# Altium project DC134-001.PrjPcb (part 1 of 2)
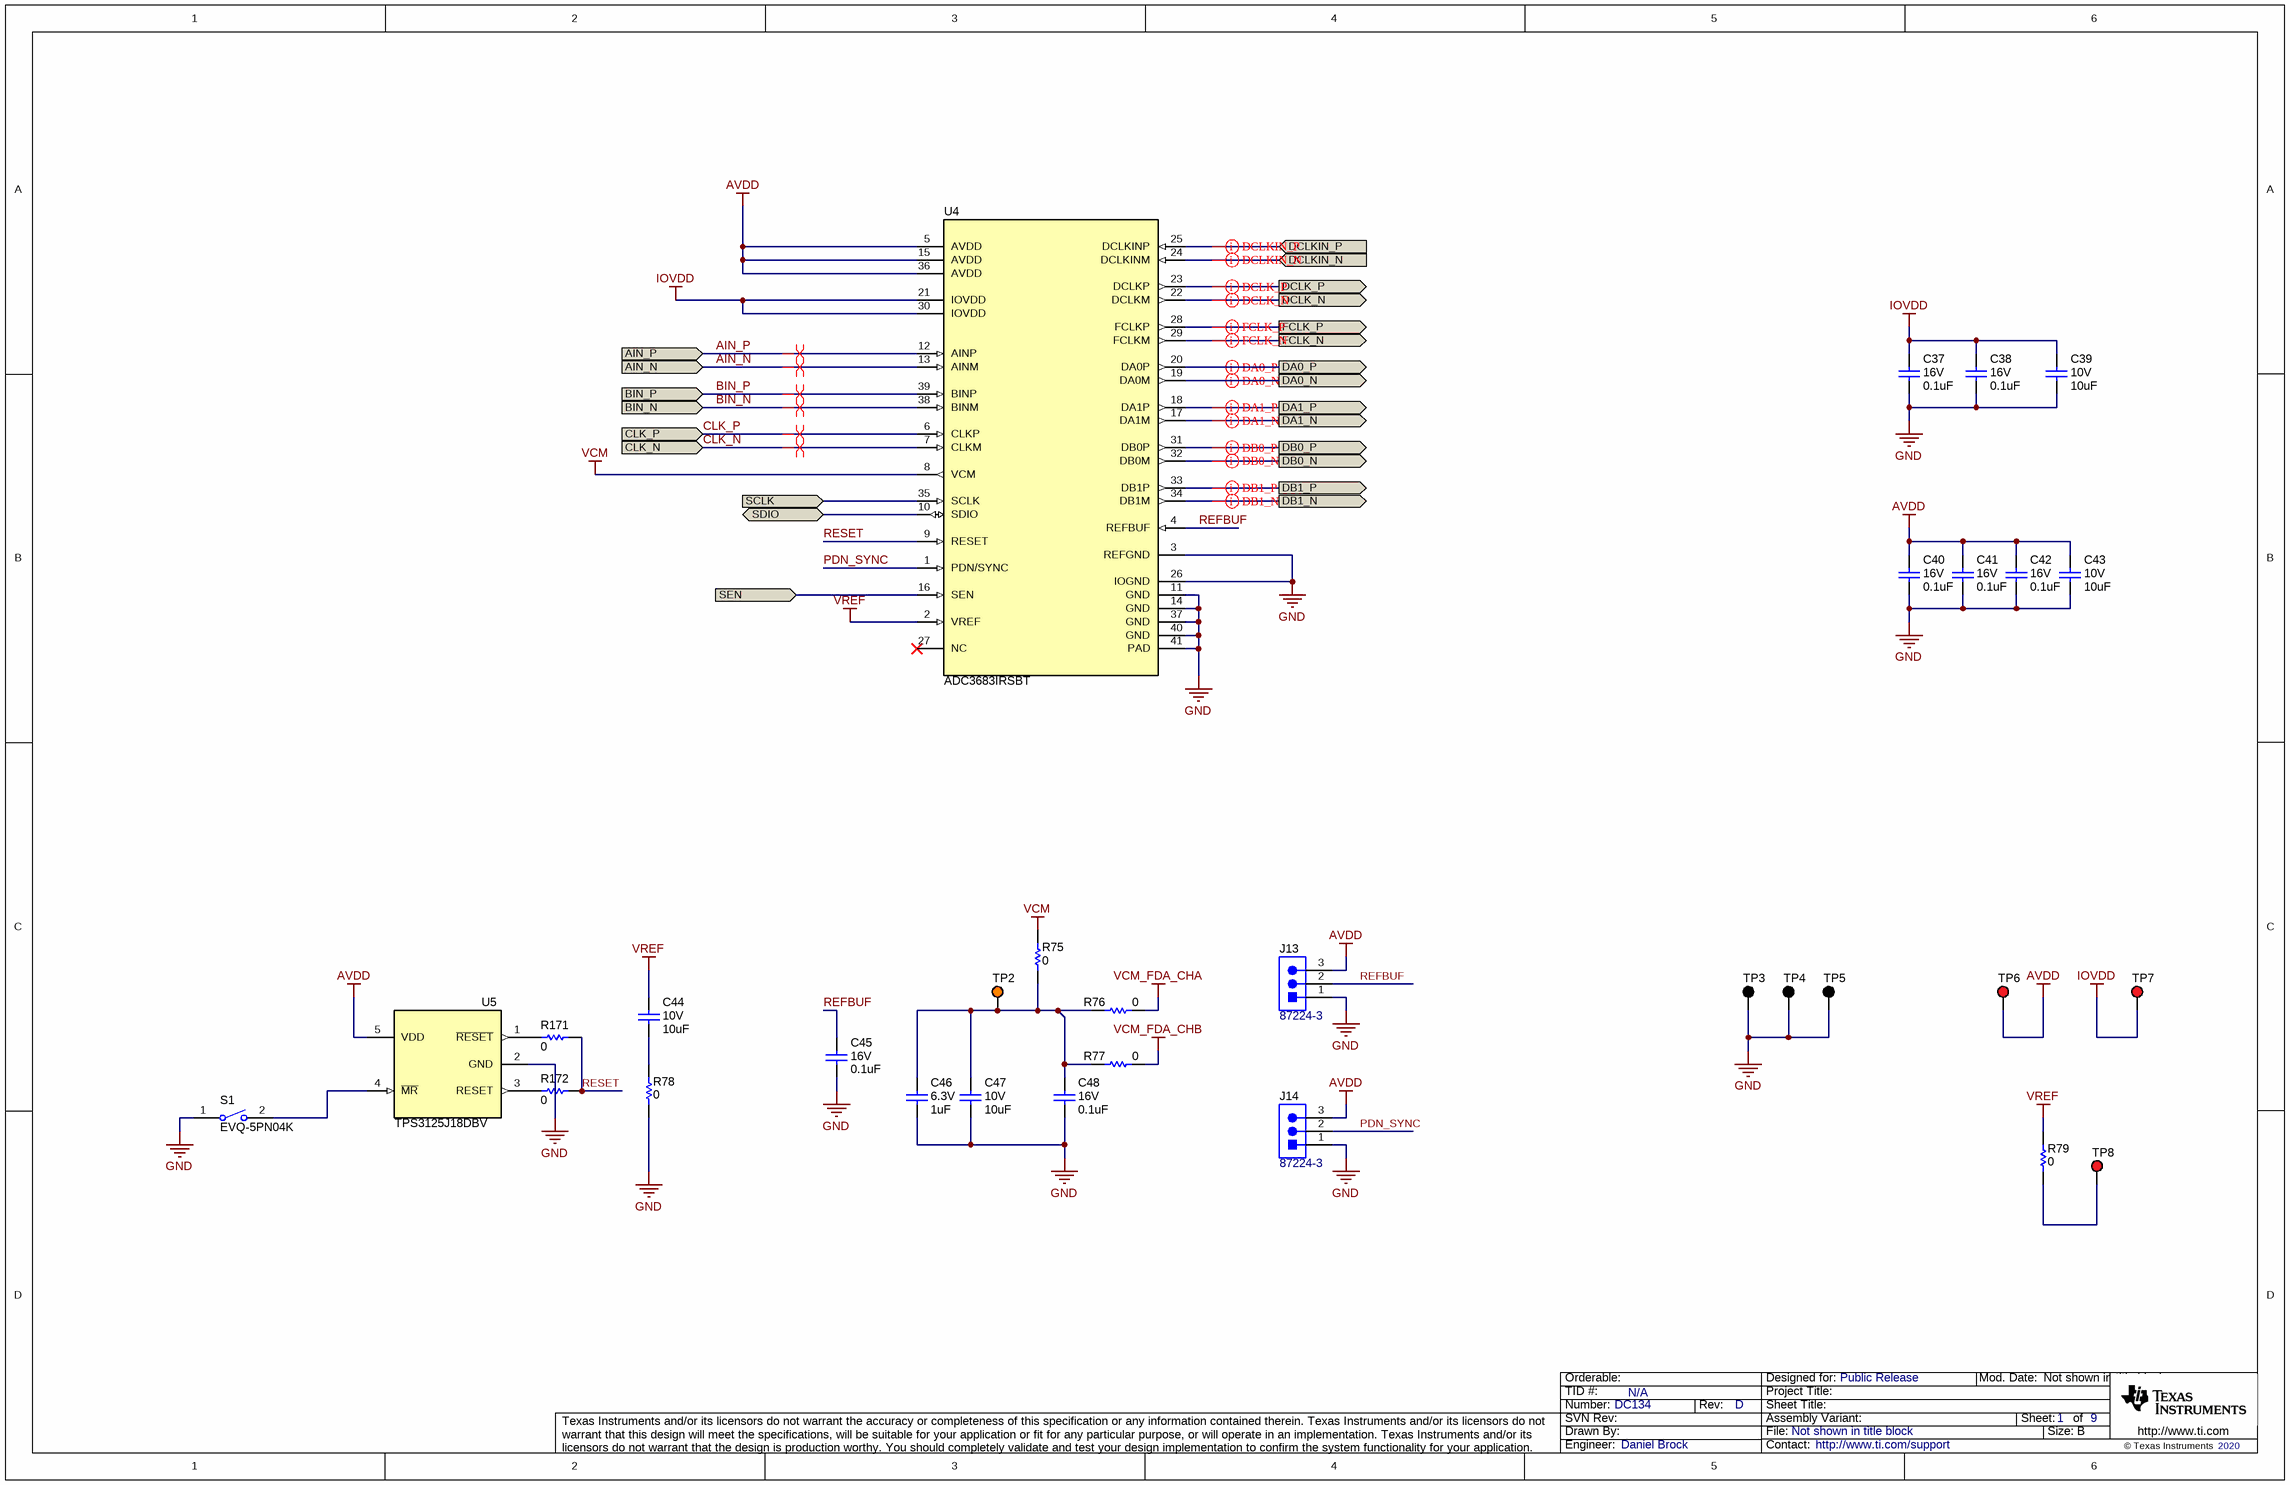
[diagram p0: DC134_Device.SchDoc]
CopyrightYear: 2020; PCB_Layout: Daniel Brock; PCB_Rev: D; PRA: ADC3683EVM; PRJ_Customer: Public Release; PRJ_Engineer: Daniel Brock; PRJ_Number: DC134; SCH_Rev: D; TechSupport: http://www.ti.com/support; TID: N/A
9 sheets, 407 parts. Net scope: flat (ports and power ports of the same name join across sheets).
Board file: DC134_PCB.PcbDoc
Sheets:
  DC134_Device.SchDoc
  DC134_AIN.SchDoc
  DC134_FDA.SchDoc
  DC134_CLK.SchDoc
  DC134_USB.SchDoc
  DC134_Power.SchDoc
  DC134_Reference.SchDoc
  DC134_FMC.SchDoc
  DC134_Hardware.SchDoc

## Sheet DC134_Device.SchDoc
size 431 x 279 mm; Date: Not shown in title block; ApprovedBy: Not shown in title block; CheckedBy: Not shown in title block; Author: Not shown in title block; CompanyName: Not shown in title block; Engineer: Not shown in title block; Organization: Not shown in title block; Address1: Not shown in title block; Address2: Not shown in title block; Address3: Not shown in title block; Address4: Not shown in title block; DocumentNumber: 1; Revision: Use project parameter SCH_Rev; SheetNumber: 1; SheetTotal: 9; PageSetup: Record=PageOptions¦CenterHorizontal=True¦CenterVertical=True¦PrintScale=1.00¦XCorrection=1.00¦YCorrection=1.00¦PrintKind=0¦BorderSize=5000000¦LeftOffset=0¦BottomOffset=0¦Orientation=2¦PaperLength=1000¦PaperWidth=1000¦Scale=100¦PaperSource=15¦PrintQuality=600¦MediaType=1¦DitherType=10¦PaperKind=Letter¦PrintScaleMode=1

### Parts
C37  VDC_V: 16V  ValueDisplayed: 0.1uF  [0201L]  (hidden comment: GRM033Z71C104KE14D)
C38  VDC_V: 16V  ValueDisplayed: 0.1uF  [0201L]  (hidden comment: GRM033Z71C104KE14D)
C39  VDC_V: 10V  ValueDisplayed: 10uF  [0603L]  (hidden comment: GRM188Z71A106MA73D)
C40  VDC_V: 16V  ValueDisplayed: 0.1uF  [0201L]  (hidden comment: GRM033Z71C104KE14D)
C41  VDC_V: 16V  ValueDisplayed: 0.1uF  [0201L]  (hidden comment: GRM033Z71C104KE14D)
C42  VDC_V: 16V  ValueDisplayed: 0.1uF  [0201L]  (hidden comment: GRM033Z71C104KE14D)
C43  VDC_V: 10V  ValueDisplayed: 10uF  [0603L]  (hidden comment: GRM188Z71A106MA73D)
C44  VDC_V: 10V  ValueDisplayed: 10uF  [0603L]  (hidden comment: GRM188Z71A106MA73D)
C45  VDC_V: 16V  ValueDisplayed: 0.1uF  [0201L]  (hidden comment: GRM033Z71C104KE14D)
C46  VDC_V: 6.3V  ValueDisplayed: 1uF  [0402L]  (hidden comment: GRM155R70J105MA12D)
C47  VDC_V: 10V  ValueDisplayed: 10uF  [0603L]  (hidden comment: GRM188Z71A106MA73D)
C48  VDC_V: 16V  ValueDisplayed: 0.1uF  [0201L]  (hidden comment: GRM033Z71C104KE14D)
J13  87224-3  [TE_87224-3]
J14  87224-3  [TE_87224-3]
R75  ValueDisplayed: 0  [0201L]  (hidden comment: CRCW02010000Z0ED)
R76  ValueDisplayed: 0  [0201L]  (hidden comment: CRCW02010000Z0ED)
R77  ValueDisplayed: 0  [0201L]  (hidden comment: CRCW02010000Z0ED)
R78  ValueDisplayed: 0  [0201L]  (hidden comment: ERJ-1GN0R00C)
R79  ValueDisplayed: 0  [0201]  (hidden comment: ERJ-1GN0R00C)
R171  ValueDisplayed: 0  [0603L]  (hidden comment: RC0603JR-070RL)
R172  ValueDisplayed: 0  [0603L]  (hidden comment: RC0603JR-070RL)
S1  EVQ-5PN04K  [SW_EVQ5PN04K]
TP2  5013  [Keystone5013]  (value not drawn)
TP3  5011  [Keystone5011]  (value not drawn)
TP4  5011  [Keystone5011]  (value not drawn)
TP5  5011  [Keystone5011]  (value not drawn)
TP6  5010  [Keystone5010]  (value not drawn)
TP7  5010  [Keystone5010]  (value not drawn)
TP8  5010  [Keystone5010]  (value not drawn)
U4  ADC3683IRSBT  [RSB0040B]
U5  TPS3125J18DBV  [DBV0005A_L]

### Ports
AIN_N (in), AIN_P (in), BIN_N (in), BIN_P (in), CLK_N (in), CLK_P (in), DA0_N (out), DA0_P (out), DA1_N (out), DA1_P (out), DB0_N (out), DB0_P (out), DB1_N (out), DB1_P (out), DCLK_N (out), DCLK_P (out), DCLKIN_N (in), DCLKIN_P (in), FCLK_N (out), FCLK_P (out), SCLK (in), SDIO (bidir), SEN (in)

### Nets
AVDD: C40.1 C41.1 C42.1 C43.1 J13.3 J14.3 TP6.1 U4.5(AVDD) U4.15(AVDD) U4.36(AVDD) U5.5(VDD)
GND: C37.2 C38.2 C39.2 C40.2 C41.2 C42.2 C43.2 C45.2 C46.2 C47.2 C48.2 J13.1 J14.1 R78.1 S1.1 TP3.1 TP4.1 TP5.1 U4.3(REFGND) U4.11(GND) U4.14(GND) U4.26(IOGND) U4.37(GND) U4.40(GND) U4.41(PAD) U5.2(GND)
IOVDD: C37.1 C38.1 C39.1 TP7.1 U4.21(IOVDD) U4.30(IOVDD)
VCM: R75.2 U4.8(VCM)
VCM_FDA_CHA: R76.2
VCM_FDA_CHB: R77.2
VREF: C44.1 R79.2 U4.2(VREF)
AIN_N: U4.13(AINM) ; port AIN_N
AIN_P: U4.12(AINP) ; port AIN_P
BIN_N: U4.38(BINM) ; port BIN_N
BIN_P: U4.39(BINP) ; port BIN_P
CLK_N: U4.7(CLKM) ; port CLK_N
CLK_P: U4.6(CLKP) ; port CLK_P
DA0_N: U4.19(DA0M) ; port DA0_N
DA0_P: U4.20(DA0P) ; port DA0_P
DA1_N: U4.17(DA1M) ; port DA1_N
DA1_P: U4.18(DA1P) ; port DA1_P
DB0_N: U4.32(DB0M) ; port DB0_N
DB0_P: U4.31(DB0P) ; port DB0_P
DB1_N: U4.34(DB1M) ; port DB1_N
DB1_P: U4.33(DB1P) ; port DB1_P
DCLK_N: U4.22(DCLKM) ; port DCLK_N
DCLK_P: U4.23(DCLKP) ; port DCLK_P
DCLKIN_N: U4.24(DCLKINM) ; port DCLKIN_N
DCLKIN_P: U4.25(DCLKINP) ; port DCLKIN_P
FCLK_N: U4.29(FCLKM) ; port FCLK_N
FCLK_P: U4.28(FCLKP) ; port FCLK_P
PDN_SYNC: J14.2 U4.1(PDN/SYNC)
REFBUF: C45.1 J13.2 U4.4(REFBUF)
RESET: R171.2 R172.2 U4.9(RESET)
SCLK: U4.35(SCLK) ; port SCLK
SDIO: U4.10(SDIO) ; port SDIO
SEN: U4.16(SEN) ; port SEN
NetC44_2: C44.2 R78.2
NetC46_1: C46.1 C47.1 C48.1 R75.1 R76.1 R77.1 TP2.1
NetR79_1: R79.1 TP8.1
NetR171_1: R171.1 U5.1(~{RESET})
NetR172_1: R172.1 U5.3(RESET)
NetS1_2: S1.2 U5.4(~{MR})

Not connected (* = marked no-connect by the designer): U4 27(NC)*

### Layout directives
differential pair: AIN_N, AIN_P, BIN_N, BIN_P, CLK_N, CLK_P, DA0_N, DA0_P, DA1_N, DA1_P, DB0_N, DB0_P, DB1_N, DB1_P, DCLK_N, DCLK_P, DCLKIN_N, DCLKIN_P, FCLK_N, FCLK_P

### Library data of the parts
C37 C38 C40-C42 C45 C48 = CMP-0064970-1: CAP, CERM, 0.1 uF, 16 V,+/- 10%, X7R, 0201; Manufacturer: MuRata; TaMin_C: -55°C; Polarized: N; SizeAreaWB_mm2: 2.08; Value1: Unknown; U/M: EA; Value: 0.1uF; TaMax_C: 125°C; SizeZ_mm: 0.26; SizeX_mm: 0.6; SizeY_mm: 0.3; Cap_Case: 0201; SizeArea_mm2: 0.18; CompType: Capacitor; Cap_F: 100nF; AEC Category: Q200
C39 C43 C44 C47 = CMP-0007497-5: CAP, CERM, 10 uF, 10 V, +/- 20%, X7R, 0603; Manufacturer: MuRata; TaMin_C: -55°C; Polarized: N; SizeAreaWB_mm2: 4.68; Value1: Unknown; U/M: EA; Value: 10uF; TaMax_C: 125°C; SizeZ_mm: 1; SizeX_mm: 1.6; SizeY_mm: 0.8; Cap_Case: 0603; SizeArea_mm2: 1.28; Cap_F: 10µF; AEC Category: Q200
C46 = CMP-0006624-2: CAP, CERM, 1 uF, 6.3 V, +/- 20%, X7R, 0402; Manufacturer: MuRata; TaMin_C: -55°C; Polarized: N; SizeAreaWB_mm2: 3; Value1: Unknown; U/M: EA; Value: 1uF; TaMax_C: 125°C; SizeZ_mm: 0.6; SizeX_mm: 1; SizeY_mm: 0.5; Cap_Case: 0402; Cap_F: 1µF; AEC Category: Q200
J13 J14 = CMP-0078139-1: Header, 2.54mm, 3x1, Gold, TH; Manufacturer: TE Connectivity; Pitch_mm: 2.54; Gender: Male; Cert_UL: Y; Current_A: 3A; Voltage_V: 750V; Green_REACh: Passed; Shrouded: N; Green_Lifecycle: Active; Row_Count: 1
R75-R77 = CMP-0027008-4: RES, 0, 5%, 0.05 W, 0201; Manufacturer: Vishay-Dale; Power_W: 50mW; TempCo: ppm/C; Value_Code: 0000; Value: 0; EIA_Code: E24; SizeX_mm: 0.6; SizeY_mm: 0.3; SizeZ_mm: 0.26; Value2: 0.05W; SizeArea_mm2: 0.18; CompType: Resistor; AEC Qualified: N; AEC Category: Q200
R78 R79 = CMP-0065361-1: RES, 0, 5%, .05 W, AEC-Q200 Grade 0, 0201; Manufacturer: Panasonic; Power_W: 50mW; Green_Lifecycle: Not Set; TempCo: ppm/C; Value_Code: 0000; Green_REACh: Incomplete; U/M: EA; Value: 0; EIA_Code: E24; SizeX_mm: 0.6; SizeY_mm: 0.3; SizeZ_mm: 0.26; Value2: .05W; SizeArea_mm2: 0.18; CompType: Resistor; AEC Qualified: Y; AEC Category: Q200
R171 R172 = CMP-0025885-5: RES, 0, 5%, 0.1 W, 0603; Manufacturer: Yageo; Power_W: 100mW; TempCo: 200 ppm/C; Value_Code: 0000; Value: 0; EIA_Code: E24; SizeX_mm: 1.6; SizeZ_mm: 1; Value2: 0.1W; SizeArea_mm2: 1.28; AEC Qualified: N; VDC_V: 75V; AEC Category: Q200; SizeY_mm: 0.8; SizeAreaWB_mm2: 4.68
S1 = CMP-0002323-1: Switch, SPST-NO, Off-Mom, 0.05 A, 12 VDC, SMD; Manufacturer: Panasonic; CurrentRating_mA: 50A; PositionCount: 1; SizeX_mm: 7.2; SizeY_mm: 3.5; SizeZ_mm: 4.3; SizeArea_mm2: 25.2; VDC_V: 12V; SizeAreaWB_mm2: 50.6
TP2 = CMP-0055150-2: Test Point, Multipurpose, Orange, TH; Manufacturer: Keystone Electronics; CT: TRUE; ContactFinish: Silver; Green_REACh: Passed; CNHeader: FALSE; Green_Lifecycle: Active
TP3-TP5 = CMP-0055148-1: Test Point, Multipurpose, Black, TH; Manufacturer: Keystone; CNHeader: FALSE; Green_Lifecycle: Active; Green_REACh: Passed; ContactFinish: Silver; CT: TRUE
TP6-TP8 = CMP-0055147-2: Test Point, Multipurpose, Red, TH; Manufacturer: Keystone Electronics; CT: TRUE; ContactFinish: Silver; Green_Lifecycle: Active; CNHeader: FALSE; Green_REACh: Passed
U4 = CMP-0080419-4: 18-bit 65 MSPS Low Noise Ultra-low Power Dual Channel ADC, RSB0040B (WQFN-40); Alternate Manufacturer: Texas Instruments; SizeArea_mm2: 25; SizeZ_mm: 0.8; AEC Category: Q200; SizeY_mm: 5; SizeAreaWB_mm2: 49; AEC Qualified: N; CompType: IC
U5 = cmp00115: Push-pull, supply voltage supervisor with manual reset; Manufacturer: Texas Instruments; CompType: Voltage Detector

## Sheet DC134_AIN.SchDoc
size 431 x 279 mm; Date: Not shown in title block; ApprovedBy: Not shown in title block; CheckedBy: Not shown in title block; Author: Not shown in title block; CompanyName: Not shown in title block; Engineer: Not shown in title block; Organization: Not shown in title block; Address1: Not shown in title block; Address2: Not shown in title block; Address3: Not shown in title block; Address4: Not shown in title block; DocumentNumber: 2; Revision: Use project parameter SCH_Rev; SheetNumber: 2; SheetTotal: 9; PageSetup: Record=PageOptions¦CenterHorizontal=True¦CenterVertical=True¦PrintScale=1.00¦XCorrection=1.00¦YCorrection=1.00¦PrintKind=0¦BorderSize=5000000¦LeftOffset=0¦BottomOffset=0¦Orientation=2¦PaperLength=1000¦PaperWidth=1000¦Scale=100¦PaperSource=15¦PrintQuality=600¦MediaType=1¦DitherType=10¦PaperKind=Letter¦PrintScaleMode=1
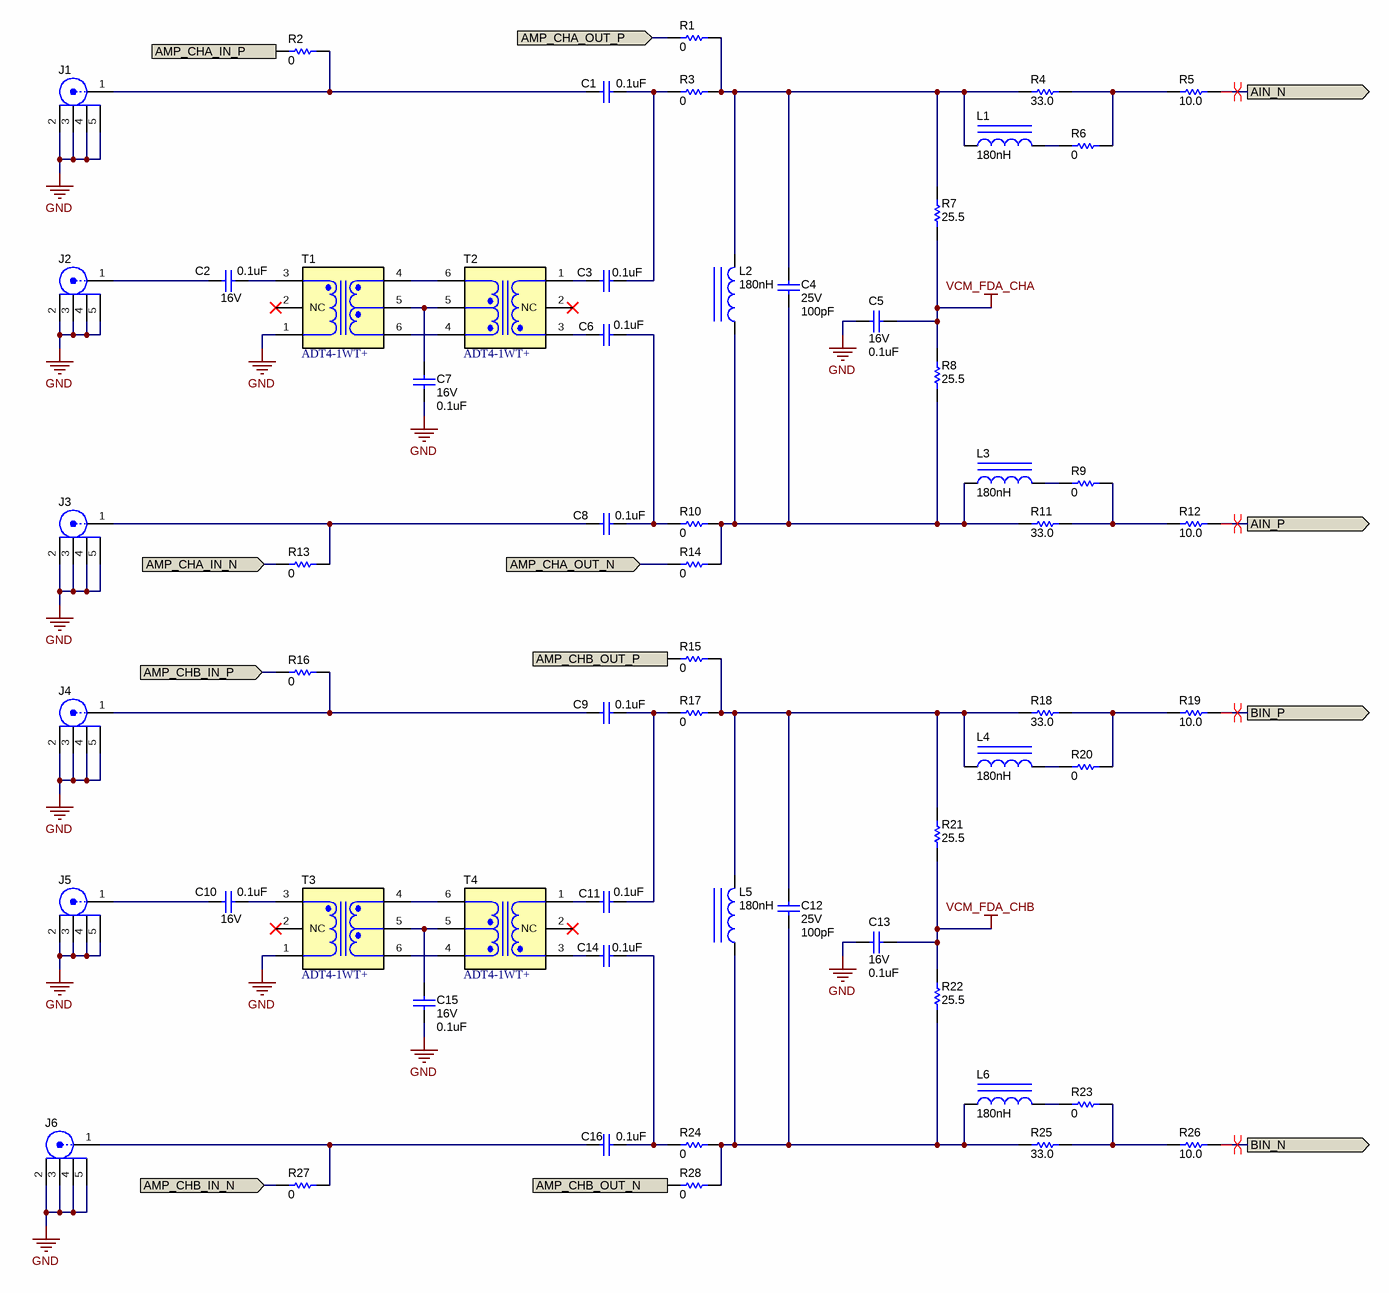
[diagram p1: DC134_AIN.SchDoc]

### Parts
C1  ValueDisplayed: 0.1uF  [0201L]  (hidden comment: GRM033Z71C104KE14D)
C2  VDC_V: 16V  ValueDisplayed: 0.1uF  [0201L]  (hidden comment: GRM033Z71C104KE14D)
C3  ValueDisplayed: 0.1uF  [0201L]  (hidden comment: GRM033Z71C104KE14D)
C4  VDC_V: 25V  ValueDisplayed: 100pF  [0201]  (hidden comment: GRM033R71E101KA01D)
C5  VDC_V: 16V  ValueDisplayed: 0.1uF  [0201L]  (hidden comment: GRM033Z71C104KE14D)
C6  ValueDisplayed: 0.1uF  [0201L]  (hidden comment: GRM033Z71C104KE14D)
C7  VDC_V: 16V  ValueDisplayed: 0.1uF  [0201L]  (hidden comment: GRM033Z71C104KE14D)
C8  ValueDisplayed: 0.1uF  [0201L]  (hidden comment: GRM033Z71C104KE14D)
C9  ValueDisplayed: 0.1uF  [0201L]  (hidden comment: GRM033Z71C104KE14D)
C10  VDC_V: 16V  ValueDisplayed: 0.1uF  [0201L]  (hidden comment: GRM033Z71C104KE14D)
C11  ValueDisplayed: 0.1uF  [0201L]  (hidden comment: GRM033Z71C104KE14D)
C12  VDC_V: 25V  ValueDisplayed: 100pF  [0201]  (hidden comment: GRM033R71E101KA01D)
C13  VDC_V: 16V  ValueDisplayed: 0.1uF  [0201L]  (hidden comment: GRM033Z71C104KE14D)
C14  ValueDisplayed: 0.1uF  [0201L]  (hidden comment: GRM033Z71C104KE14D)
C15  VDC_V: 16V  ValueDisplayed: 0.1uF  [0201L]  (hidden comment: GRM033Z71C104KE14D)
C16  ValueDisplayed: 0.1uF  [0201L]  (hidden comment: GRM033Z71C104KE14D)
J1  142-0701-801  [Johnson_142-0701-801]  (value not drawn)
J2  901-144-8RFX  [AMPHENOL_901-144-8RFX]  (value not drawn)
J3  142-0701-801  [Johnson_142-0701-801]  (value not drawn)
J4  142-0701-801  [Johnson_142-0701-801]  (value not drawn)
J5  901-144-8RFX  [AMPHENOL_901-144-8RFX]  (value not drawn)
J6  142-0701-801  [Johnson_142-0701-801]  (value not drawn)
L1  ValueDisplayed: 180nH  [IND_LQG15H]  (hidden comment: LQG15HSR18J02D)
L2  ValueDisplayed: 180nH  [IND_LQG15H]  (hidden comment: LQG15HSR18J02D)
L3  ValueDisplayed: 180nH  [IND_LQG15H]  (hidden comment: LQG15HSR18J02D)
L4  ValueDisplayed: 180nH  [IND_LQG15H]  (hidden comment: LQG15HSR18J02D)
L5  ValueDisplayed: 180nH  [IND_LQG15H]  (hidden comment: LQG15HSR18J02D)
L6  ValueDisplayed: 180nH  [IND_LQG15H]  (hidden comment: LQG15HSR18J02D)
R1  ValueDisplayed: 0  [0201L]  (hidden comment: CRCW02010000Z0ED)
R2  ValueDisplayed: 0  [0201L]  (hidden comment: CRCW02010000Z0ED)
R3  ValueDisplayed: 0  [0201L]  (hidden comment: CRCW02010000Z0ED)
R4  ValueDisplayed: 33.0  [0201]  (hidden comment: RC0201FR-7D33RL)
R5  ValueDisplayed: 10.0  [0201]  (hidden comment: RC0201FR-7D10RL)
R6  ValueDisplayed: 0  [0201L]  (hidden comment: CRCW02010000Z0ED)
R7  ValueDisplayed: 25.5  [0201L]  (hidden comment: RC0201FR-0725R5L)
R8  ValueDisplayed: 25.5  [0201L]  (hidden comment: RC0201FR-0725R5L)
R9  ValueDisplayed: 0  [0201L]  (hidden comment: CRCW02010000Z0ED)
R10  ValueDisplayed: 0  [0201L]  (hidden comment: CRCW02010000Z0ED)
R11  ValueDisplayed: 33.0  [0201]  (hidden comment: RC0201FR-7D33RL)
R12  ValueDisplayed: 10.0  [0201]  (hidden comment: RC0201FR-7D10RL)
R13  ValueDisplayed: 0  [0201L]  (hidden comment: CRCW02010000Z0ED)
R14  ValueDisplayed: 0  [0201L]  (hidden comment: CRCW02010000Z0ED)
R15  ValueDisplayed: 0  [0201L]  (hidden comment: CRCW02010000Z0ED)
R16  ValueDisplayed: 0  [0201L]  (hidden comment: CRCW02010000Z0ED)
R17  ValueDisplayed: 0  [0201L]  (hidden comment: CRCW02010000Z0ED)
R18  ValueDisplayed: 33.0  [0201]  (hidden comment: RC0201FR-7D33RL)
R19  ValueDisplayed: 10.0  [0201]  (hidden comment: RC0201FR-7D10RL)
R20  ValueDisplayed: 0  [0201L]  (hidden comment: CRCW02010000Z0ED)
R21  ValueDisplayed: 25.5  [0201L]  (hidden comment: RC0201FR-0725R5L)
R22  ValueDisplayed: 25.5  [0201L]  (hidden comment: RC0201FR-0725R5L)
R23  ValueDisplayed: 0  [0201L]  (hidden comment: CRCW02010000Z0ED)
R24  ValueDisplayed: 0  [0201L]  (hidden comment: CRCW02010000Z0ED)
R25  ValueDisplayed: 33.0  [0201]  (hidden comment: RC0201FR-7D33RL)
R26  ValueDisplayed: 10.0  [0201]  (hidden comment: RC0201FR-7D10RL)
R27  ValueDisplayed: 0  [0201L]  (hidden comment: CRCW02010000Z0ED)
R28  ValueDisplayed: 0  [0201L]  (hidden comment: CRCW02010000Z0ED)
T1  ADT4-1WT+  [MNC_CD542]
T2  ADT4-1WT+  [MNC_CD542]
T3  ADT4-1WT+  [MNC_CD542]
T4  ADT4-1WT+  [MNC_CD542]

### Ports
AIN_N (out), AIN_P (out), AMP_CHA_IN_N (in), AMP_CHA_IN_P (in), AMP_CHA_OUT_N (in), AMP_CHA_OUT_P (in), AMP_CHB_IN_N (in), AMP_CHB_IN_P (in), AMP_CHB_OUT_N (in), AMP_CHB_OUT_P (in), BIN_N (out), BIN_P (out)

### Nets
GND: C5.1 C7.1 C13.1 C15.1 J1.2 J1.3 J1.4 J1.5 J2.2 J2.3 J2.4 J2.5 J3.2 J3.3 J3.4 J3.5 J4.2 J4.3 J4.4 J4.5 J5.2 J5.3 J5.4 J5.5 J6.2 J6.3 J6.4 J6.5 T1.1 T3.1
VCM_FDA_CHA: C5.2 R7.1 R8.2
VCM_FDA_CHB: C13.2 R21.1 R22.2
AIN_N: R5.2 ; port AIN_N
AIN_P: R12.2 ; port AIN_P
AMP_CHA_IN_N: R13.1 ; port AMP_CHA_IN_N
AMP_CHA_IN_P: R2.1 ; port AMP_CHA_IN_P
AMP_CHA_OUT_N: R14.1 ; port AMP_CHA_OUT_N
AMP_CHA_OUT_P: R1.1 ; port AMP_CHA_OUT_P
AMP_CHB_IN_N: R27.1 ; port AMP_CHB_IN_N
AMP_CHB_IN_P: R16.1 ; port AMP_CHB_IN_P
AMP_CHB_OUT_N: R28.1 ; port AMP_CHB_OUT_N
AMP_CHB_OUT_P: R15.1 ; port AMP_CHB_OUT_P
BIN_N: R26.2 ; port BIN_N
BIN_P: R19.2 ; port BIN_P
NetC1_1: C1.1 J1.1 R2.2
NetC1_2: C1.2 C3.2 R3.1
NetC2_1: C2.1 J2.1
NetC2_2: C2.2 T1.3
NetC3_1: C3.1 T2.1
NetC4_1: C4.1 L1.1 L2.2 R1.2 R3.2 R4.1 R7.2
NetC4_2: C4.2 L2.1 L3.1 R8.1 R10.2 R11.1 R14.2
NetC6_1: C6.1 T2.3
NetC6_2: C6.2 C8.2 R10.1
NetC7_2: C7.2 T1.5 T2.5
NetC8_1: C8.1 J3.1 R13.2
NetC9_1: C9.1 J4.1 R16.2
NetC9_2: C9.2 C11.2 R17.1
NetC10_1: C10.1 J5.1
NetC10_2: C10.2 T3.3
NetC11_1: C11.1 T4.1
NetC12_1: C12.1 L4.1 L5.2 R15.2 R17.2 R18.1 R21.2
NetC12_2: C12.2 L5.1 L6.1 R22.1 R24.2 R25.1 R28.2
NetC14_1: C14.1 T4.3
NetC14_2: C14.2 C16.2 R24.1
NetC15_2: C15.2 T3.5 T4.5
NetC16_1: C16.1 J6.1 R27.2
NetL1_2: L1.2 R6.1
NetL3_2: L3.2 R9.1
NetL4_2: L4.2 R20.1
NetL6_2: L6.2 R23.1
NetR4_2: R4.2 R5.1 R6.2
NetR9_2: R9.2 R11.2 R12.1
NetR18_2: R18.2 R19.1 R20.2
NetR23_2: R23.2 R25.2 R26.1
NetT1_4: T1.4 T2.6
NetT1_6: T1.6 T2.4
NetT3_4: T3.4 T4.6
NetT3_6: T3.6 T4.4

Not connected (* = marked no-connect by the designer): T1 2(NC)*; T2 2(NC)*; T3 2(NC)*; T4 2(NC)*

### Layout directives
differential pair: AIN_N, AIN_P, BIN_N, BIN_P

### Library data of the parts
C1 C3 C6 C8 C9 C11 C14 C16 = CMP-0064970-1: CAP, CERM, 0.1 uF, 16 V,+/- 10%, X7R, 0201; Manufacturer: MuRata; TaMin_C: -55°C; Polarized: N; SizeAreaWB_mm2: 2.08; Value1: Unknown; U/M: EA; Value: 0.1uF; TaMax_C: 125°C; SizeZ_mm: 0.26; SizeX_mm: 0.6; SizeY_mm: 0.3; Cap_Case: 0201; Value2: 16V; SizeArea_mm2: 0.18; CompType: Capacitor; Cap_F: 100nF; AEC Category: Q200
C2 C5 C7 C10 C13 C15 = CMP-0064970-1: as C37 on sheet DC134_Device
C4 C12 = CMP-0009763-1: CAP, CERM, 100 pF, 25 V, +/- 10%, X7R, 0201; Manufacturer: MuRata; TaMin_C: -55°C; Polarized: N; SizeAreaWB_mm2: 2.08; Value1: Unknown; U/M: EA; Value: 100pF; TaMax_C: 125°C; SizeZ_mm: 0.26; SizeX_mm: 0.6; SizeY_mm: 0.3; SizeArea_mm2: 0.18; AEC Category: Q200
J1 J3 J4 J6 = CMP-0055828-1: Connector, End launch SMA, 50 ohm, SMT; Manufacturer: Cinch Connectivity; CNHeader: FALSE; Green_Lifecycle: Not Set; Green_REACh: Incomplete; CT: TRUE
J2 J5 = CMP-0055833-1: SMA Straight Jack, Gold, 50 Ohm, TH; Manufacturer: Amphenol RF; CNHeader: FALSE; Green_Lifecycle: Not Set; Green_REACh: Incomplete; CT: TRUE
L1-L6 = CMP-0058650-1: Inductor, Multilayer, Air Core, 180 nH, 0.14 A, 3.38 ohm, SMD; Manufacturer: MuRata; Isat: 0.14A @ % inductance drop; Irms: 0.14A @ C rise; Green_Lifecycle: Active; SizeAreaWB_mm2: 3; DCR_ohm: 3.38; Green_REACh: Passed; Value: 180nH; Imax_A: 140mA; SizeZ_mm: 0.55; SizeX_mm: 1; SizeY_mm: 0.5; Value2: 0.14A; AEC Category: Q200
R1-R3 R6 R9 R10 R13-R17 R20 R23 R24 R27 R28 = CMP-0027008-4: RES, 0, 5%, 0.05 W, 0201; Manufacturer: Vishay-Dale; Power_W: 50mW; TempCo: ppm/C; Value_Code: 0000; Value: 0; EIA_Code: E24; SizeX_mm: 0.6; SizeY_mm: 0.3; SizeZ_mm: 0.26; Value2: 0.05W; SizeArea_mm2: 0.18; AEC Qualified: N; AEC Category: Q200
R4 R11 R18 R25 = CMP-0028006-1: RES, 33.0, 1%, 0.05 W, 0201; Manufacturer: Yageo America; Power_W: 50mW; TempCo: 200 ppm/C; Value_Code: 33R0; U/M: EA; Value: 33.0; Res_ohm: 33; SizeX_mm: 0.6; SizeY_mm: 0.3; SizeZ_mm: 0.26; Value2: 0.05W; SizeArea_mm2: 0.18; AEC Qualified: N; VDC_V: 25V; AEC Category: Q200
R5 R12 R19 R26 = CMP-0027946-1: RES, 10.0, 1%, 0.05 W, 0201; Manufacturer: Yageo America; Power_W: 50mW; TempCo: 350 ppm/C; Value_Code: 10R0; U/M: EA; Value: 10.0; EIA_Code: E96; Res_ohm: 10; SizeX_mm: 0.6; SizeY_mm: 0.3; SizeZ_mm: 0.26; Value2: 0.05W; SizeArea_mm2: 0.18; AEC Qualified: N; VDC_V: 25V; AEC Category: Q200
R7 R8 R21 R22 = CMP-0027524-1: RES, 25.5, 1%, 0.05 W, 0201; Manufacturer: Yageo America; Power_W: 50mW; TempCo: 200 ppm/C; Value_Code: 25R5; U/M: EA; Value: 25.5; EIA_Code: E96; SizeX_mm: 0.6; SizeY_mm: 0.3; SizeZ_mm: 0.26; Value2: 0.05W; SizeArea_mm2: 0.18; CompType: Resistor; AEC Qualified: N; VDC_V: 25V; AEC Category: Q200
T1-T4 = CMP-0030461-2: RF Transformer, 50 ohm, 2 to 775 MHz, SMT; Manufacturer: Minicircuits; Green_REACh: Incomplete; Green_Lifecycle: Not Set

## Sheet DC134_FDA.SchDoc
size 431 x 279 mm; Date: Not shown in title block; ApprovedBy: Not shown in title block; CheckedBy: Not shown in title block; Author: Not shown in title block; CompanyName: Not shown in title block; Engineer: Not shown in title block; Organization: Not shown in title block; Address1: Not shown in title block; Address2: Not shown in title block; Address3: Not shown in title block; Address4: Not shown in title block; DocumentNumber: 3; Revision: Use project parameter SCH_Rev; SheetNumber: 3; SheetTotal: 9; PageSetup: Record=PageOptions¦CenterHorizontal=True¦CenterVertical=True¦PrintScale=1.00¦XCorrection=1.00¦YCorrection=1.00¦PrintKind=0¦BorderSize=5000000¦LeftOffset=0¦BottomOffset=0¦Orientation=2¦PaperLength=1000¦PaperWidth=1000¦Scale=100¦PaperSource=15¦PrintQuality=600¦MediaType=1¦DitherType=10¦PaperKind=Letter¦PrintScaleMode=1
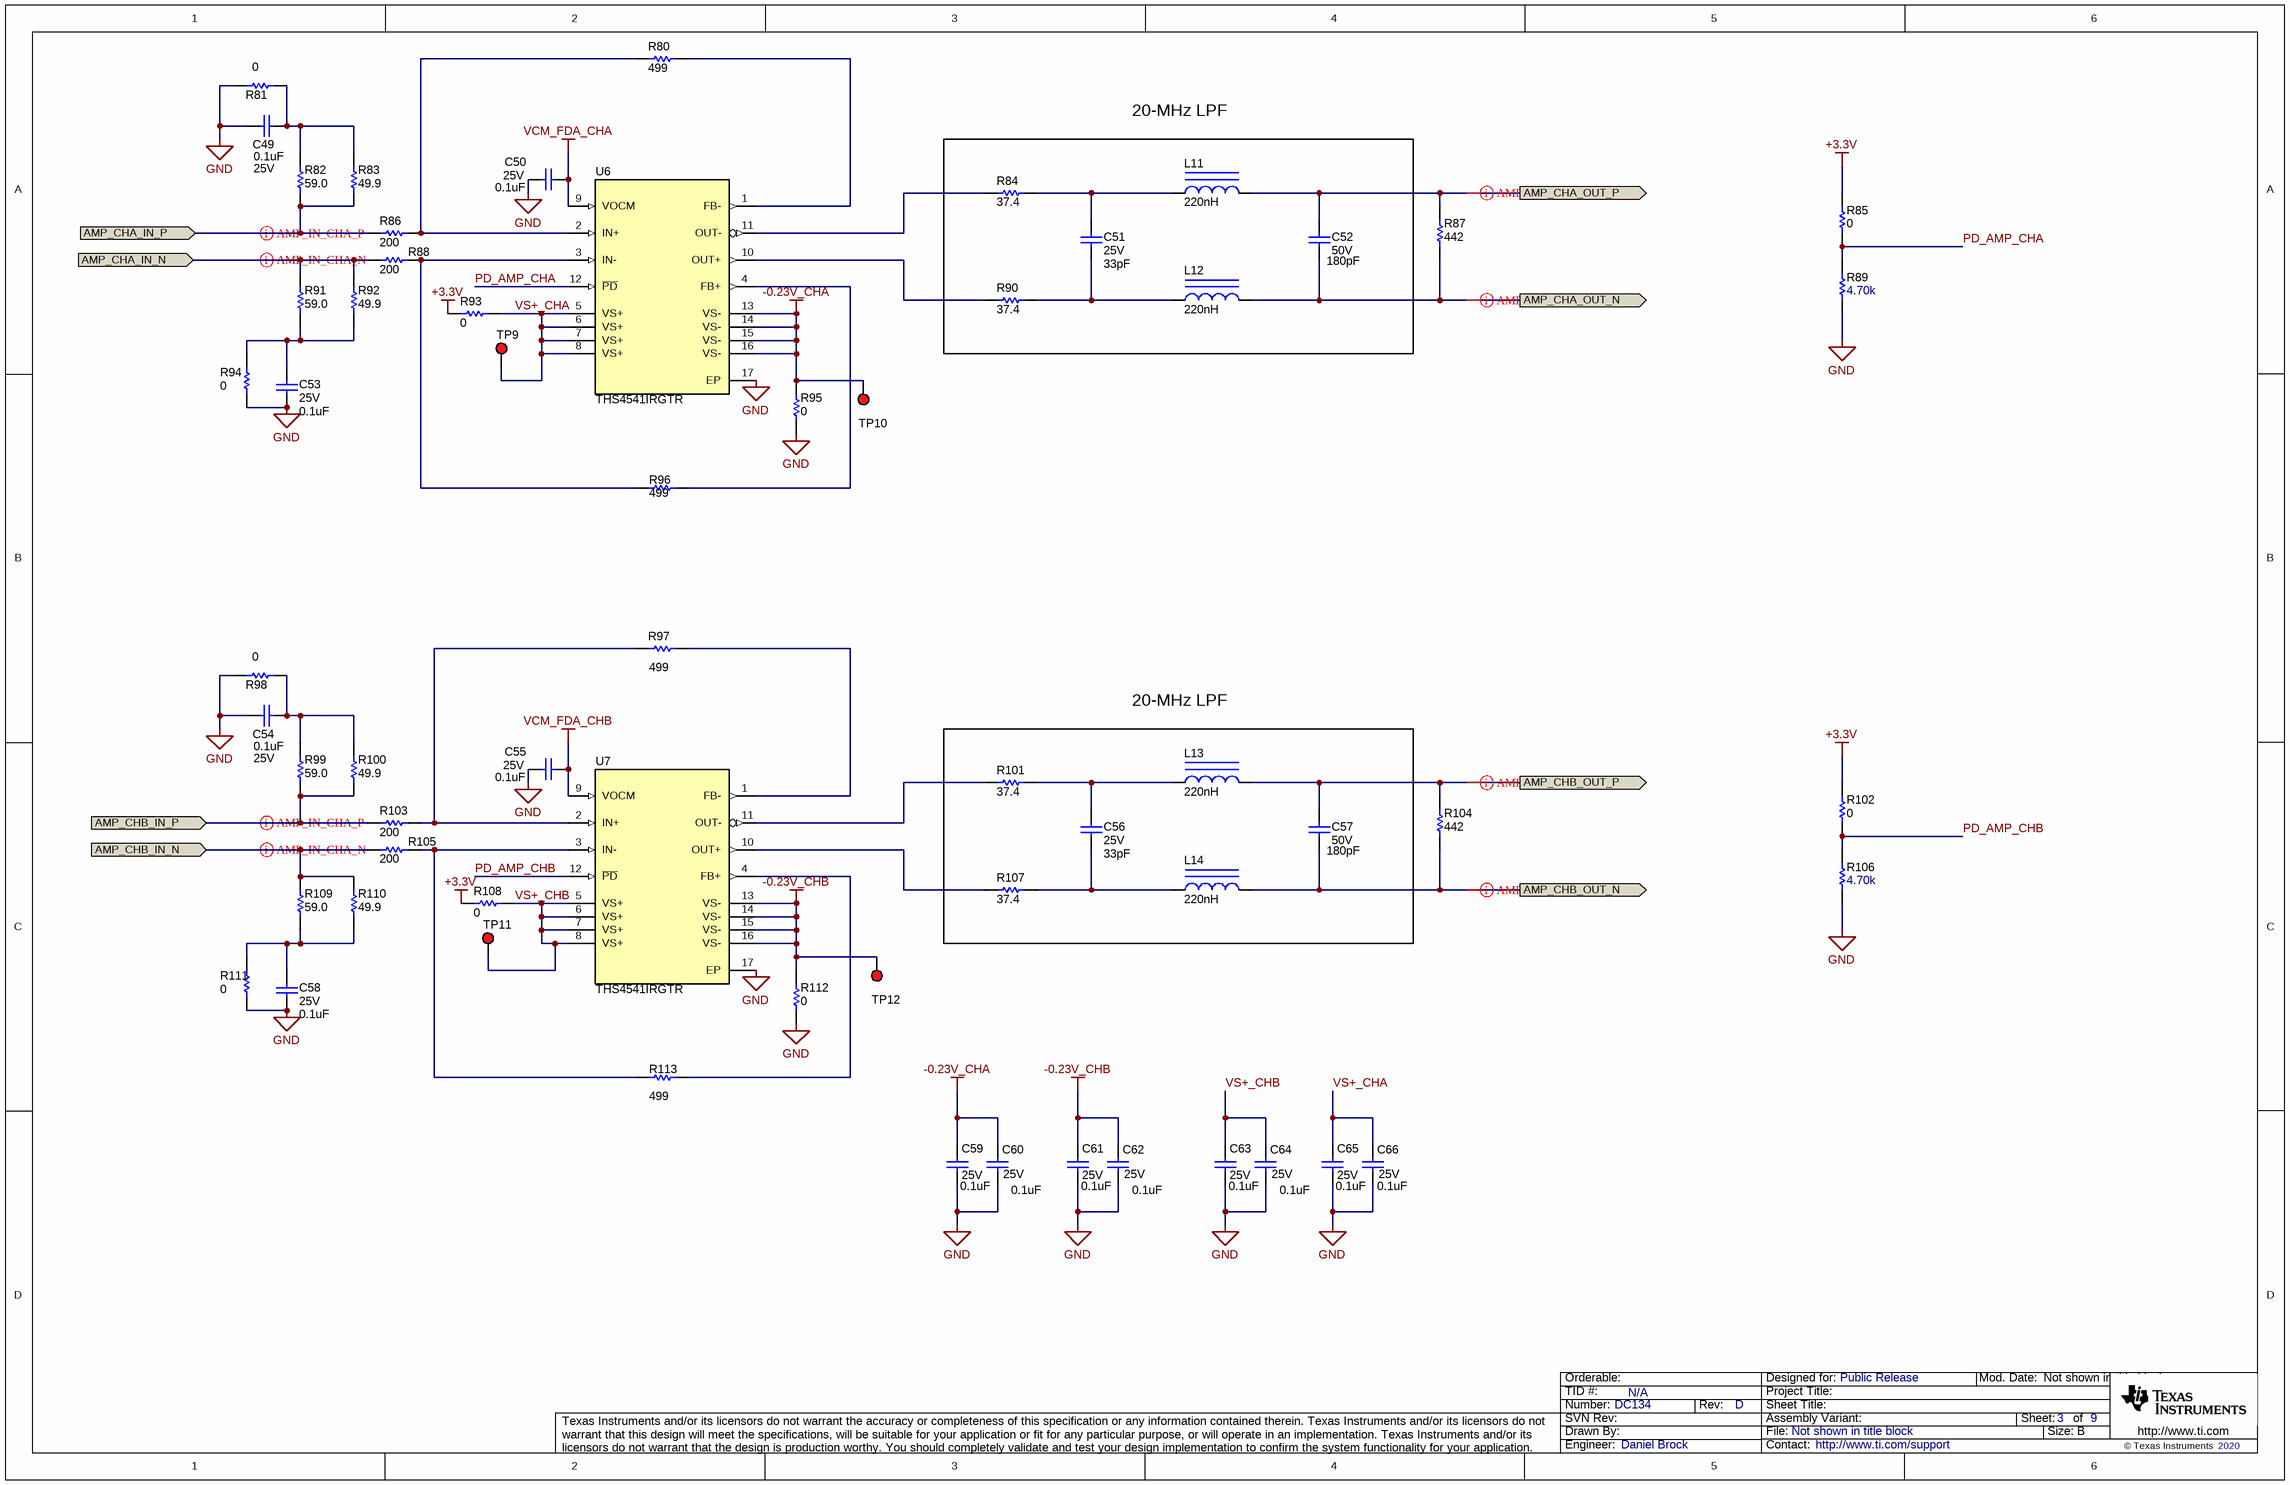
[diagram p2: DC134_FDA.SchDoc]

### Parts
C49  VDC_V: 25V  ValueDisplayed: 0.1uF  [0402]  (hidden comment: GRM155R61E104KA87D)
C50  VDC_V: 25V  ValueDisplayed: 0.1uF  [0402]  (hidden comment: GRM155R61E104KA87D)
C51  VDC_V: 25V  ValueDisplayed: 33pF  [0402]  (hidden comment: GRM1555C1E330JA01D)
C52  VDC_V: 50V  ValueDisplayed: 180pF  [0402]  (hidden comment: GRM1555C1H181JA01D)
C53  VDC_V: 25V  ValueDisplayed: 0.1uF  [0402]  (hidden comment: GRM155R61E104KA87D)
C54  VDC_V: 25V  ValueDisplayed: 0.1uF  [0402]  (hidden comment: GRM155R61E104KA87D)
C55  VDC_V: 25V  ValueDisplayed: 0.1uF  [0402]  (hidden comment: GRM155R61E104KA87D)
C56  VDC_V: 25V  ValueDisplayed: 33pF  [0402]  (hidden comment: GRM1555C1E330JA01D)
C57  VDC_V: 50V  ValueDisplayed: 180pF  [0402]  (hidden comment: GRM1555C1H181JA01D)
C58  VDC_V: 25V  ValueDisplayed: 0.1uF  [0402]  (hidden comment: GRM155R61E104KA87D)
C59  VDC_V: 25V  ValueDisplayed: 0.1uF  [0402]  (hidden comment: GRM155R61E104KA87D)
C60  value 0.1uF  VDC_V: 25V  [0402]  (hidden comment: GRM155R61E104KA87D)
C61  VDC_V: 25V  ValueDisplayed: 0.1uF  [0402]  (hidden comment: GRM155R61E104KA87D)
C62  value 0.1uF  VDC_V: 25V  [0402]  (hidden comment: GRM155R61E104KA87D)
C63  VDC_V: 25V  ValueDisplayed: 0.1uF  [0402]  (hidden comment: GRM155R61E104KA87D)
C64  value 0.1uF  VDC_V: 25V  [0402]  (hidden comment: GRM155R61E104KA87D)
C65  VDC_V: 25V  ValueDisplayed: 0.1uF  [0402]  (hidden comment: GRM155R61E104KA87D)
C66  VDC_V: 25V  ValueDisplayed: 0.1uF  [0402]  (hidden comment: GRM155R61E104KA87D)
L11  ValueDisplayed: 220nH  [IND_LQG15H]  (hidden comment: LQG15HSR22J02D)
L12  ValueDisplayed: 220nH  [IND_LQG15H]  (hidden comment: LQG15HSR22J02D)
L13  ValueDisplayed: 220nH  [IND_LQG15H]  (hidden comment: LQG15HSR22J02D)
L14  ValueDisplayed: 220nH  [IND_LQG15H]  (hidden comment: LQG15HSR22J02D)
R80  ValueDisplayed: 499  [0402]  (hidden comment: CRCW0402499RFKED)
R81  ValueDisplayed: 0  [0402]  (hidden comment: CRCW04020000Z0ED)
R82  ValueDisplayed: 59.0  [0402]  (hidden comment: CRCW040259R0FKED)
R83  ValueDisplayed: 49.9  [0402]  (hidden comment: CRCW040249R9FKED)
R84  ValueDisplayed: 37.4  [0402]  (hidden comment: CRCW040237R4FKED)
R85  ValueDisplayed: 0  [0402]  (hidden comment: CRCW04020000Z0ED)
R86  ValueDisplayed: 200  [0402]  (hidden comment: CRCW0402200RFKED)
R87  ValueDisplayed: 442  [0402]  (hidden comment: CRCW0402442RFKED)
R88  ValueDisplayed: 200  [0402]  (hidden comment: CRCW0402200RFKED)
R89  ValueDisplayed: 4.70k  [0402]  (hidden comment: ERJ-2RKF4701X)
R90  ValueDisplayed: 37.4  [0402]  (hidden comment: CRCW040237R4FKED)
R91  ValueDisplayed: 59.0  [0402]  (hidden comment: CRCW040259R0FKED)
R92  ValueDisplayed: 49.9  [0402]  (hidden comment: CRCW040249R9FKED)
R93  ValueDisplayed: 0  [0201L]  (hidden comment: CRCW02010000Z0ED)
R94  ValueDisplayed: 0  [0402]  (hidden comment: CRCW04020000Z0ED)
R95  ValueDisplayed: 0  [0201L]  (hidden comment: CRCW02010000Z0ED)
R96  ValueDisplayed: 499  [0402]  (hidden comment: CRCW0402499RFKED)
R97  ValueDisplayed: 499  [0402]  (hidden comment: CRCW0402499RFKED)
R98  ValueDisplayed: 0  [0402]  (hidden comment: CRCW04020000Z0ED)
R99  ValueDisplayed: 59.0  [0402]  (hidden comment: CRCW040259R0FKED)
R100  ValueDisplayed: 49.9  [0402]  (hidden comment: CRCW040249R9FKED)
R101  ValueDisplayed: 37.4  [0402]  (hidden comment: CRCW040237R4FKED)
R102  ValueDisplayed: 0  [0402]  (hidden comment: CRCW04020000Z0ED)
R103  ValueDisplayed: 200  [0402]  (hidden comment: CRCW0402200RFKED)
R104  ValueDisplayed: 442  [0402]  (hidden comment: CRCW0402442RFKED)
R105  ValueDisplayed: 200  [0402]  (hidden comment: CRCW0402200RFKED)
R106  ValueDisplayed: 4.70k  [0402]  (hidden comment: ERJ-2RKF4701X)
R107  ValueDisplayed: 37.4  [0402]  (hidden comment: CRCW040237R4FKED)
R108  ValueDisplayed: 0  [0201L]  (hidden comment: CRCW02010000Z0ED)
R109  ValueDisplayed: 59.0  [0402]  (hidden comment: CRCW040259R0FKED)
R110  ValueDisplayed: 49.9  [0402]  (hidden comment: CRCW040249R9FKED)
R111  ValueDisplayed: 0  [0402]  (hidden comment: CRCW04020000Z0ED)
R112  ValueDisplayed: 0  [0201L]  (hidden comment: CRCW02010000Z0ED)
R113  Res_ohm: 499  [0402]  (hidden comment: CRCW0402499RFKED)
TP9  5010  [Keystone5010]  (value not drawn)
TP10  5010  [Keystone5010]  (value not drawn)
TP11  5010  [Keystone5010]  (value not drawn)
TP12  5010  [Keystone5010]  (value not drawn)
U6  THS4541IRGTR  [RGT0016A_NV]
U7  THS4541IRGTR  [RGT0016A_NV]

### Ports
AMP_CHA_IN_N (in), AMP_CHA_IN_P (in), AMP_CHA_OUT_N (out), AMP_CHA_OUT_P (out), AMP_CHB_IN_N (in), AMP_CHB_IN_P (in), AMP_CHB_OUT_N (out), AMP_CHB_OUT_P (out)

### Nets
+3.3V: R85.2 R93.2 R102.2 R108.2
-0.23V_CHA: C59.1 C60.1 R95.2 TP10.1 U6.13(VS-) U6.14(VS-) U6.15(VS-) U6.16(VS-)
-0.23V_CHB: C61.1 C62.1 R112.2 TP12.1 U7.13(VS-) U7.14(VS-) U7.15(VS-) U7.16(VS-)
GND: C49.1 C50.1 C53.2 C54.1 C55.1 C58.2 C59.2 C60.2 C61.2 C62.2 C63.2 C64.2 C65.2 C66.2 R81.2 R89.1 R94.2 R95.1 R98.2 R106.1 R111.2 R112.1 U6.17(EP) U7.17(EP)
VCM_FDA_CHA: C50.2 U6.9(VOCM)
VCM_FDA_CHB: C55.2 U7.9(VOCM)
AMP_CHA_IN_N: R88.1 R91.2 R92.2 ; port AMP_CHA_IN_N
AMP_CHA_IN_P: R82.1 R83.1 R86.1 ; port AMP_CHA_IN_P
AMP_CHA_OUT_N: C52.2 L12.2 R87.1 ; port AMP_CHA_OUT_N
AMP_CHA_OUT_P: C52.1 L11.2 R87.2 ; port AMP_CHA_OUT_P
AMP_CHB_IN_N: R105.1 R109.2 R110.2 ; port AMP_CHB_IN_N
AMP_CHB_IN_P: R99.1 R100.1 R103.1 ; port AMP_CHB_IN_P
AMP_CHB_OUT_N: C57.2 L14.2 R104.1 ; port AMP_CHB_OUT_N
AMP_CHB_OUT_P: C57.1 L13.2 R104.2 ; port AMP_CHB_OUT_P
PD_AMP_CHA: R85.1 R89.2 U6.12(~{PD})
PD_AMP_CHB: R102.1 R106.2 U7.12(~{PD})
VS+_CHA: C65.1 C66.1 R93.1 TP9.1 U6.5(VS+) U6.6(VS+) U6.7(VS+) U6.8(VS+)
VS+_CHB: C63.1 C64.1 R108.1 TP11.1 U7.5(VS+) U7.6(VS+) U7.7(VS+) U7.8(VS+)
NetC49_2: C49.2 R81.1 R82.2 R83.2
NetC51_1: C51.1 L11.1 R84.2
NetC51_2: C51.2 L12.1 R90.2
NetC53_1: C53.1 R91.1 R92.1 R94.1
NetC54_2: C54.2 R98.1 R99.2 R100.2
NetC56_1: C56.1 L13.1 R101.2
NetC56_2: C56.2 L14.1 R107.2
NetC58_1: C58.1 R109.1 R110.1 R111.1
NetR80_1: R80.1 R86.2 U6.2(IN+)
NetR80_2: R80.2 U6.1(FB-)
NetR84_1: R84.1 U6.11(OUT-)
NetR88_2: R88.2 R96.1 U6.3(IN-)
NetR90_1: R90.1 U6.10(OUT+)
NetR96_2: R96.2 U6.4(FB+)
NetR97_1: R97.1 R103.2 U7.2(IN+)
NetR97_2: R97.2 U7.1(FB-)
NetR101_1: R101.1 U7.11(OUT-)
NetR105_2: R105.2 R113.1 U7.3(IN-)
NetR107_1: R107.1 U7.10(OUT+)
NetR113_2: R113.2 U7.4(FB+)

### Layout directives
differential pair: AMP_CHA_IN_N, AMP_CHA_IN_P, AMP_CHA_OUT_N, AMP_CHA_OUT_P, AMP_CHB_IN_N, AMP_CHB_IN_P, AMP_CHB_OUT_N, AMP_CHB_OUT_P

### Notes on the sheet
- 20-MHz LPF

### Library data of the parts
C49 C50 C54 C55 = CMP-0006607-2: CAP, CERM, 0.1 uF, 25 V, +/- 10%, X5R, 0402; Manufacturer: MuRata; TaMin_C: -55°C; Polarized: N; SizeAreaWB_mm2: 3; Value1: Unknown; U/M: EA; Value: 0.1uF; TaMax_C: 85°C; SizeZ_mm: 0.6; SizeX_mm: 1; SizeY_mm: 0.5; CompType: Capacitor; Cap_F: 100nF; AEC Category: Q200
C51 C56 = CMP-0006377-2: CAP, CERM, 33 pF, 25 V, +/- 5%, C0G/NP0, 0402; Manufacturer: MuRata; TaMin_C: -55°C; Polarized: N; SizeAreaWB_mm2: 3; Value1: Unknown; U/M: EA; Value: 33pF; TaMax_C: 125°C; SizeZ_mm: 0.6; SizeX_mm: 1; SizeY_mm: 0.5; AEC Category: Q200
C52 C57 = CMP-0006425-2: CAP, CERM, 180 pF, 50 V, +/- 5%, C0G/NP0, 0402; Manufacturer: MuRata; TaMin_C: -55°C; Polarized: N; SizeAreaWB_mm2: 3; Value1: Unknown; U/M: EA; Value: 180pF; TaMax_C: 125°C; SizeZ_mm: 0.6; SizeX_mm: 1; SizeY_mm: 0.5; AEC Category: Q200
C53 C58 C59 C61 C63 C65 C66 = CMP-0006607-2: CAP, CERM, 0.1 uF, 25 V, +/- 10%, X5R, 0402; Manufacturer: MuRata; TaMin_C: -55°C; Polarized: N; SizeAreaWB_mm2: 3; Value1: Unknown; U/M: EA; Value: 0.1uF; TaMax_C: 85°C; SizeZ_mm: 0.6; SizeX_mm: 1; SizeY_mm: 0.5; Cap_F: 100nF; AEC Category: Q200
C60 C62 C64 = CMP-0006607-2: CAP, CERM, 0.1 uF, 25 V, +/- 10%, X5R, 0402; Manufacturer: MuRata; TaMin_C: -55°C; Polarized: N; SizeAreaWB_mm2: 3; Value1: Unknown; U/M: EA; TaMax_C: 85°C; SizeZ_mm: 0.6; SizeX_mm: 1; SizeY_mm: 0.5; Cap_F: 100nF; AEC Category: Q200
L11-L14 = CMP-0058651-1: Inductor, Multilayer, Air Core, 220 nH, 0.12 A, 3.77 ohm, SMD; Manufacturer: MuRata; Isat: 0.12A @ % inductance drop; Irms: 0.12A @ C rise; Green_Lifecycle: Active; SizeAreaWB_mm2: 3; DCR_ohm: 3.77; Green_REACh: Passed; Value: 220nH; Imax_A: 1.2dA; SizeZ_mm: 0.55; SizeX_mm: 1; SizeY_mm: 0.5; Value2: 0.12A; AEC Category: Q200
R80 R96 R97 R113 = CMP-0026402-2: RES, 499, 1%, 0.063 W, AEC-Q200 Grade 0, 0402; Manufacturer: Vishay-Dale; Power_W: 63mW; TempCo: 100 ppm/C; Value_Code: 499R; Value: 499; EIA_Code: E96; SizeX_mm: 1; SizeY_mm: 0.5; SizeZ_mm: 0.6; Value2: 0.063W; AEC Qualified: Y; VDC_V: 50V; AEC Category: Q200; AEC Grade: 0
R81 R85 R94 R98 R102 R111 = CMP-0026822-3: RES, 0, 5%, 0.063 W, AEC-Q200 Grade 0, 0402; Manufacturer: Vishay-Dale; Power_W: 63mW; TempCo: 200 ppm/C; Value_Code: 0000; Value: 0; EIA_Code: E24; SizeX_mm: 1; SizeY_mm: 0.5; SizeZ_mm: 0.6; Value2: 0.063W; AEC Qualified: Y; VDC_V: 50V; AEC Category: Q200
R82 R91 R99 R109 = CMP-0026462-2: RES, 59.0, 1%, 0.063 W, AEC-Q200 Grade 0, 0402; Manufacturer: Vishay-Dale; Power_W: 63mW; TempCo: 100 ppm/C; Value_Code: 59R0; Value: 59.0; EIA_Code: E96; Res_ohm: 59; SizeX_mm: 1; SizeY_mm: 0.5; Value2: 0.063W; AEC Qualified: Y; VDC_V: 50V; AEC Category: Q200; AEC Grade: 0; SizeZ_mm: 0.6
R83 R92 R100 R110 = CMP-0026404-2: RES, 49.9, 1%, 0.063 W, AEC-Q200 Grade 0, 0402; Manufacturer: Vishay-Dale; Power_W: 63mW; TempCo: 100 ppm/C; Value_Code: 49R9; Value: 49.9; EIA_Code: E96; SizeX_mm: 1; SizeY_mm: 0.5; SizeZ_mm: 0.6; Value2: 0.063W; AEC Qualified: Y; VDC_V: 50V; AEC Category: Q200; AEC Grade: 0
R84 R90 R101 R107 = CMP-0026320-2: RES, 37.4, 1%, 0.063 W, AEC-Q200 Grade 0, 0402; Manufacturer: Vishay-Dale; Power_W: 63mW; TempCo: 100 ppm/C; Value_Code: 37R4; Value: 37.4; EIA_Code: E96; SizeX_mm: 1; SizeY_mm: 0.5; SizeZ_mm: 0.6; Value2: 0.063W; AEC Qualified: Y; VDC_V: 50V; AEC Category: Q200; AEC Grade: 0
R86 R88 R103 R105 = CMP-0026159-2: RES, 200, 1%, 0.063 W, AEC-Q200 Grade 0, 0402; Manufacturer: Vishay-Dale; Power_W: 63mW; TempCo: 100 ppm/C; Value_Code: 200R; Value: 200; EIA_Code: E96; SizeX_mm: 1; SizeY_mm: 0.5; SizeZ_mm: 0.6; Value2: 0.063W; AEC Qualified: Y; VDC_V: 50V; AEC Category: Q200; AEC Grade: 0
R87 R104 = CMP-0026382-2: RES, 442, 1%, 0.063 W, AEC-Q200 Grade 0, 0402; Manufacturer: Vishay-Dale; Power_W: 63mW; TempCo: 100 ppm/C; Value_Code: 442R; Value: 442; EIA_Code: E96; SizeX_mm: 1; SizeY_mm: 0.5; SizeZ_mm: 0.6; Value2: 0.063W; AEC Qualified: Y; VDC_V: 50V; AEC Category: Q200; AEC Grade: 0
R89 R106 = CMP-0026700-1: RES, 4.70 k, 1%, 0.1 W, 0402; Manufacturer: Panasonic; Power_W: 100mW; TempCo: 100 ppm/C; Value_Code: 4k70; U/M: EA; Value: 4.70k; Res_ohm: 4.7k; SizeX_mm: 1; SizeY_mm: 0.5; SizeZ_mm: 0.6; Value2: 0.1W; CompType: Resistor; VDC_V: 50V; AEC Category: Q200
R93 R95 R108 R112 = CMP-0027008-4: as R1 on sheet DC134_AIN
TP9-TP12 = CMP-0055147-2: as TP6 on sheet DC134_Device
U6 U7 = CMP-0065559-3: High-Speed Differential I/O Amplifier, RGT0016A (VQFN-16); Alternate PartNumber: THS4541IRGTT; Manufacturer: Texas Instruments; SizeZ_mm: 4; SizeArea_mm2: 16; CompType: IC; SizeAreaWB_mm2: 25; AEC Category: Q200; AEC Qualified: N

## Sheet DC134_CLK.SchDoc
size 431 x 279 mm; Date: Not shown in title block; ApprovedBy: Not shown in title block; CheckedBy: Not shown in title block; Author: Not shown in title block; CompanyName: Not shown in title block; Engineer: Not shown in title block; Organization: Not shown in title block; Address1: Not shown in title block; Address2: Not shown in title block; Address3: Not shown in title block; Address4: Not shown in title block; DocumentNumber: 4; Revision: Use project parameter SCH_Rev; SheetNumber: 4; SheetTotal: 9; PageSetup: Record=PageOptions¦CenterHorizontal=True¦CenterVertical=True¦PrintScale=1.00¦XCorrection=1.00¦YCorrection=1.00¦PrintKind=0¦BorderSize=5000000¦LeftOffset=0¦BottomOffset=0¦Orientation=2¦PaperLength=1000¦PaperWidth=1000¦Scale=100¦PaperSource=15¦PrintQuality=600¦MediaType=1¦DitherType=10¦PaperKind=Letter¦PrintScaleMode=1
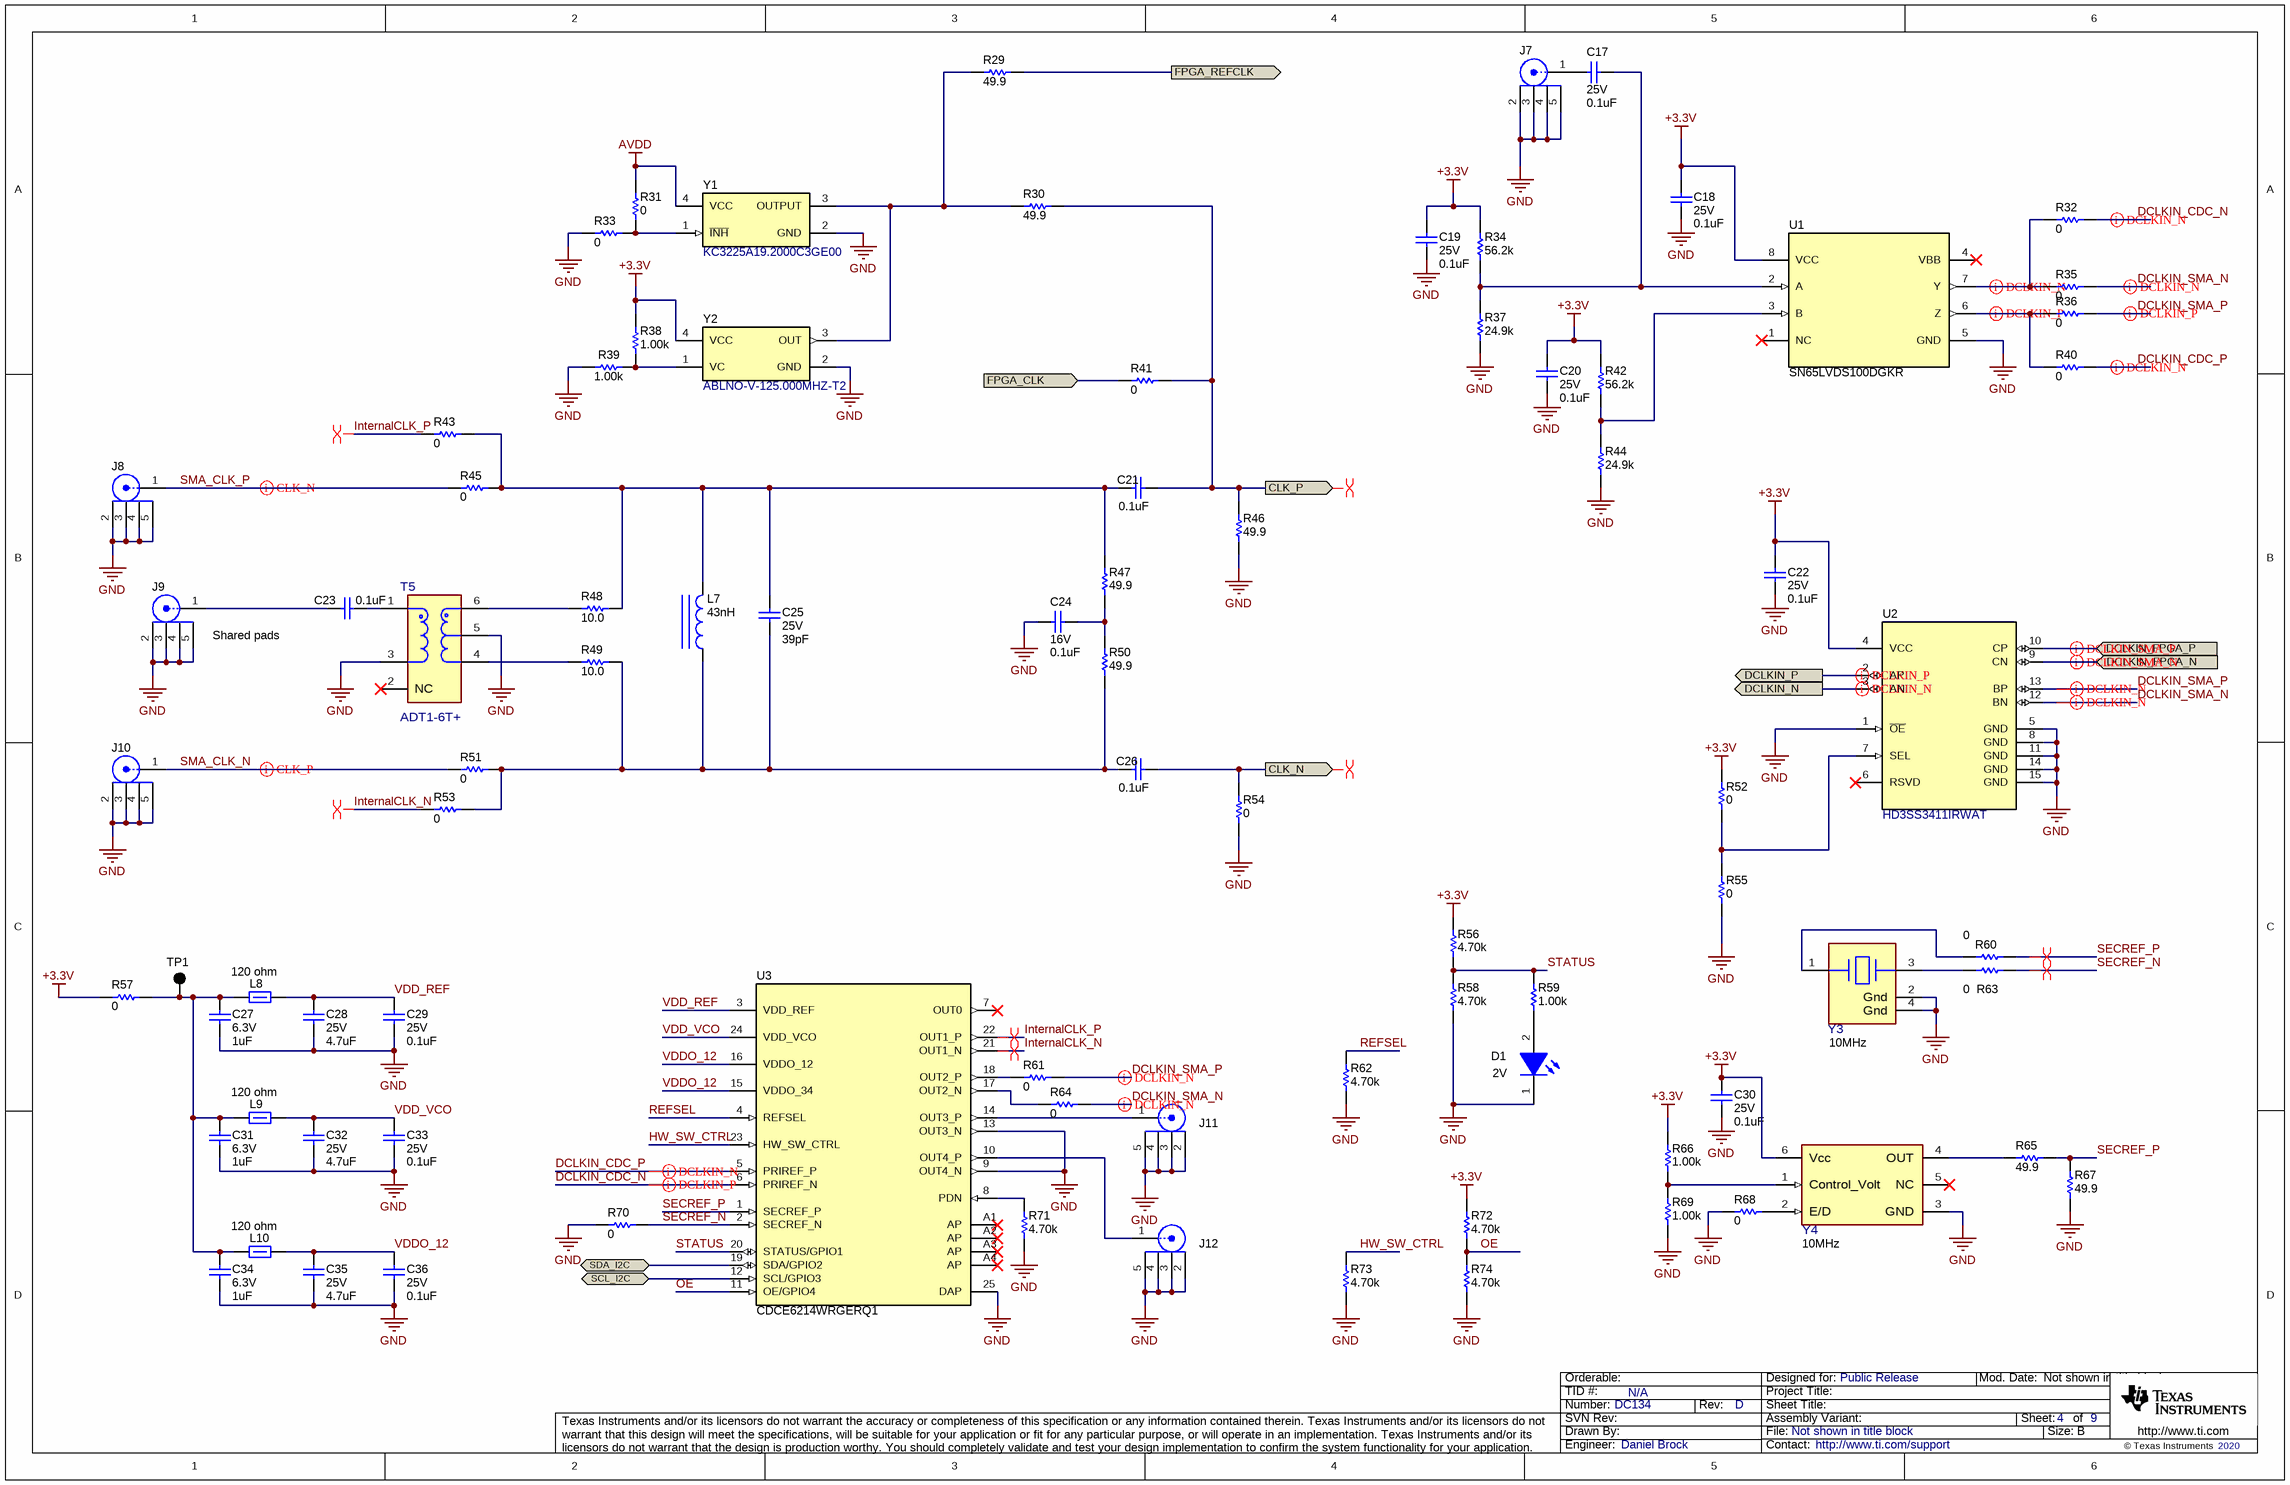
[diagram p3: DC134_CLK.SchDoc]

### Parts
C17  VDC_V: 25V  ValueDisplayed: 0.1uF  [0402]  (hidden comment: GRM155R61E104KA87D)
C18  VDC_V: 25V  ValueDisplayed: 0.1uF  [0402]  (hidden comment: GRM155R61E104KA87D)
C19  VDC_V: 25V  ValueDisplayed: 0.1uF  [0402]  (hidden comment: GRM155R61E104KA87D)
C20  VDC_V: 25V  ValueDisplayed: 0.1uF  [0402]  (hidden comment: GRM155R61E104KA87D)
C21  ValueDisplayed: 0.1uF  [0201L]  (hidden comment: GRM033Z71C104KE14D)
C22  VDC_V: 25V  ValueDisplayed: 0.1uF  [0402]  (hidden comment: GRM155R61E104KA87D)
C23  ValueDisplayed: 0.1uF  [0201L]  (hidden comment: GRM033Z71C104KE14D)
C24  VDC_V: 16V  ValueDisplayed: 0.1uF  [0201L]  (hidden comment: GRM033Z71C104KE14D)
C25  VDC_V: 25V  ValueDisplayed: 39pF  [0402]  (hidden comment: GRM1555C1E390JA01D)
C26  ValueDisplayed: 0.1uF  [0201L]  (hidden comment: GRM033Z71C104KE14D)
C27  VDC_V: 6.3V  ValueDisplayed: 1uF  [0402]  (hidden comment: GRM152R60J105ME15D)
C28  VDC_V: 25V  ValueDisplayed: 4.7uF  [0603]  (hidden comment: GRM188R61E475KE11D)
C29  VDC_V: 25V  ValueDisplayed: 0.1uF  [0201_033]  (hidden comment: GRM033R61E104KE14J)
C30  VDC_V: 25V  ValueDisplayed: 0.1uF  [0201_033]  (hidden comment: GRM033R61E104KE14J)
C31  VDC_V: 6.3V  ValueDisplayed: 1uF  [0402]  (hidden comment: GRM152R60J105ME15D)
C32  VDC_V: 25V  ValueDisplayed: 4.7uF  [0603]  (hidden comment: GRM188R61E475KE11D)
C33  VDC_V: 25V  ValueDisplayed: 0.1uF  [0201_033]  (hidden comment: GRM033R61E104KE14J)
C34  VDC_V: 6.3V  ValueDisplayed: 1uF  [0402]  (hidden comment: GRM152R60J105ME15D)
C35  VDC_V: 25V  ValueDisplayed: 4.7uF  [0603]  (hidden comment: GRM188R61E475KE11D)
C36  VDC_V: 25V  ValueDisplayed: 0.1uF  [0201_033]  (hidden comment: GRM033R61E104KE14J)
D1  Value2: 2V  [LTST-C150_1206_Green]  (hidden comment: LTST-C150KGKT)
J7  901-144-8RFX  [AMPHENOL_901-144-8RFX]  (value not drawn)
J8  142-0701-801  [Johnson_142-0701-801]  (value not drawn)
J9  901-144-8RFX  [AMPHENOL_901-144-8RFX]  (value not drawn)
J10  142-0701-801  [Johnson_142-0701-801]  (value not drawn)
J11  901-144-8RFX  [AMPHENOL_901-144-8RFX]  (value not drawn)
J12  901-144-8RFX  [AMPHENOL_901-144-8RFX]  (value not drawn)
L7  ValueDisplayed: 43nH  [LQG15WZ_02]  (hidden comment: LQG15WZ43NG02D)
L8  value 120 ohm  [0603]  (hidden comment: BLM18KG121TH1D)
L9  value 120 ohm  [0603]  (hidden comment: BLM18KG121TH1D)
L10  value 120 ohm  [0603]  (hidden comment: BLM18KG121TH1D)
R29  ValueDisplayed: 49.9  [0201L]  (hidden comment: RC0201FR-7D49R9L)
R30  ValueDisplayed: 49.9  [0201L]  (hidden comment: RC0201FR-7D49R9L)
R31  ValueDisplayed: 0  [0201L]  (hidden comment: CRCW02010000Z0ED)
R32  ValueDisplayed: 0  [0201L]  (hidden comment: CRCW02010000Z0ED)
R33  ValueDisplayed: 0  [0201L]  (hidden comment: CRCW02010000Z0ED)
R34  ValueDisplayed: 56.2k  [0402]  (hidden comment: CRCW040256K2FKED)
R35  ValueDisplayed: 0  [0201L]  (hidden comment: CRCW02010000Z0ED)
R36  ValueDisplayed: 0  [0201L]  (hidden comment: CRCW02010000Z0ED)
R37  ValueDisplayed: 24.9k  [0402]  (hidden comment: CRCW040224K9FKED)
R38  ValueDisplayed: 1.00k  [0201L]  (hidden comment: RC0201FR-071KL)
R39  ValueDisplayed: 1.00k  [0201L]  (hidden comment: RC0201FR-071KL)
R40  ValueDisplayed: 0  [0201L]  (hidden comment: CRCW02010000Z0ED)
R41  ValueDisplayed: 0  [0201L]  (hidden comment: CRCW02010000Z0ED)
R42  ValueDisplayed: 56.2k  [0402]  (hidden comment: CRCW040256K2FKED)
R43  ValueDisplayed: 0  [0201L]  (hidden comment: CRCW02010000Z0ED)
R44  ValueDisplayed: 24.9k  [0402]  (hidden comment: CRCW040224K9FKED)
R45  ValueDisplayed: 0  [0201L]  (hidden comment: CRCW02010000Z0ED)
R46  ValueDisplayed: 49.9  [0201L]  (hidden comment: RC0201FR-7D49R9L)
R47  ValueDisplayed: 49.9  [0201L]  (hidden comment: RC0201FR-7D49R9L)
R48  ValueDisplayed: 10.0  [0201L]  (hidden comment: RC0201FR-7D10RL)
R49  ValueDisplayed: 10.0  [0201L]  (hidden comment: RC0201FR-7D10RL)
R50  ValueDisplayed: 49.9  [0201L]  (hidden comment: RC0201FR-7D49R9L)
R51  ValueDisplayed: 0  [0201L]  (hidden comment: CRCW02010000Z0ED)
R52  ValueDisplayed: 0  [0201L]  (hidden comment: CRCW02010000Z0ED)
R53  ValueDisplayed: 0  [0201L]  (hidden comment: CRCW02010000Z0ED)
R54  ValueDisplayed: 0  [0201L]  (hidden comment: CRCW02010000Z0ED)
R55  ValueDisplayed: 0  [0201L]  (hidden comment: CRCW02010000Z0ED)
R56  ValueDisplayed: 4.70k  [0201]  (hidden comment: RC0201FR-7D4K7L)
R57  ValueDisplayed: 0  [0603]  (hidden comment: RMCF0603ZT0R00)
R58  ValueDisplayed: 4.70k  [0201]  (hidden comment: RC0201FR-7D4K7L)
R59  ValueDisplayed: 1.00k  [0402]  (hidden comment: RC0402FR-071KL)
R60  ValueDisplayed: 0  [0201L]  (hidden comment: CRCW02010000Z0ED)
R61  ValueDisplayed: 0  [0201L]  (hidden comment: CRCW02010000Z0ED)
R62  ValueDisplayed: 4.70k  [0201]  (hidden comment: RC0201FR-7D4K7L)
R63  ValueDisplayed: 0  [0201L]  (hidden comment: CRCW02010000Z0ED)
R64  ValueDisplayed: 0  [0201L]  (hidden comment: CRCW02010000Z0ED)
R65  ValueDisplayed: 49.9  [0201L]  (hidden comment: RC0201FR-7D49R9L)
R66  ValueDisplayed: 1.00k  [0201L]  (hidden comment: RC0201FR-071KL)
R67  ValueDisplayed: 49.9  [0201L]  (hidden comment: RC0201FR-7D49R9L)
R68  ValueDisplayed: 0  [0201L]  (hidden comment: CRCW02010000Z0ED)
R69  ValueDisplayed: 1.00k  [0201L]  (hidden comment: RC0201FR-071KL)
R70  ValueDisplayed: 0  [0201L]  (hidden comment: CRCW02010000Z0ED)
R71  ValueDisplayed: 4.70k  [0201]  (hidden comment: RC0201FR-7D4K7L)
R72  ValueDisplayed: 4.70k  [0201]  (hidden comment: RC0201FR-7D4K7L)
R73  ValueDisplayed: 4.70k  [0201]  (hidden comment: RC0201FR-7D4K7L)
R74  ValueDisplayed: 4.70k  [0201]  (hidden comment: RC0201FR-7D4K7L)
T5  ADT1-6T+  [FP-ADT1-6T+_SMD6-MFG]  (value not drawn)
TP1  5011  [Keystone5011]  (value not drawn)
U1  SN65LVDS100DGKR  [DGK0008A_L]
U2  HD3SS3411IRWAT  [RWA0014A]
U3  CDCE6214WRGERQ1  [RGE0024P]
Y1  KC3225A19.2000C3GE00  [Kyocera_KC3225A]
Y2  ABLNO-V-125.000MHZ-T2  [Abracon_ABLNO]
Y3  Frequency_Fixed: 10MHz  [FP-ECS-100-12-33-AGN-TR_XTAL_SMD_3MM2_2MM5-MFG]  (hidden comment: ECS-100-12-33-AGN-TR)
Y4  Frequency_Fixed: 10MHz  [FP-CVHD-957-10.000_SMT_XTAL_14MM2_9MM14-MFG]  (hidden comment: CVHD-957-10.000)

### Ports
CLK_N (out), CLK_P (out), DCLKIN_FPGA_N (in), DCLKIN_FPGA_P (in), DCLKIN_N (out), DCLKIN_P (out), FPGA_CLK (in), FPGA_REFCLK (out), SCL_I2C (bidir), SDA_I2C (bidir)

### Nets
+3.3V: C18.2 C19.2 C20.2 C22.2 C30.1 R34.2 R38.2 R42.2 R52.2 R56.2 R57.1 R66.2 R72.2 U1.8(VCC) U2.4(VCC) Y2.4(VCC) Y4.6(Vcc)
AVDD: R31.2 Y1.4(VCC)
GND: C18.1 C19.1 C20.1 C22.1 C24.1 C27.2 C28.2 C29.2 C30.2 C31.2 C32.2 C33.2 C34.2 C35.2 C36.2 D1.1(K) J7.2 J7.3 J7.4 J7.5 J8.2 J8.3 J8.4 J8.5 J9.2 J9.3 J9.4 J9.5 J10.2 J10.3 J10.4 J10.5 J11.2 J11.3 J11.4 J11.5 J12.2 J12.3 J12.4 J12.5 R33.1 R37.1 R39.1 R44.1 R46.1 R54.1 R55.1 R58.1 R62.1 R67.1 R68.2 R69.1 R70.2 R71.1 R73.1 R74.1 T5.3 T5.5 U1.5(GND) U2.1(~{OE}) U2.5(GND) U2.8(GND) U2.11(GND) U2.14(GND) U2.15(GND) U3.9(OUT4_N) U3.13(OUT3_N) U3.25(DAP) Y1.2(GND) Y2.2(GND) Y3.2(Gnd) Y3.4(Gnd) Y4.3(GND)
CLK_N: C26.2 R54.2 ; port CLK_N
CLK_P: C21.2 R30.2 R41.2 R46.2 ; port CLK_P
DCLKIN_CDC_N: R32.2 U3.6(PRIREF_N)
DCLKIN_CDC_P: R40.2 U3.5(PRIREF_P)
DCLKIN_FPGA_N: U2.9(CN) ; port DCLKIN_FPGA_N
DCLKIN_FPGA_P: U2.10(CP) ; port DCLKIN_FPGA_P
DCLKIN_N: U2.3(AN) ; port DCLKIN_N
DCLKIN_P: U2.2(AP) ; port DCLKIN_P
DCLKIN_SMA_N: R35.2 R64.2 U2.12(BN)
DCLKIN_SMA_P: R36.2 R61.2 U2.13(BP)
FPGA_CLK: R41.1 ; port FPGA_CLK
FPGA_REFCLK: R29.2 ; port FPGA_REFCLK
HW_SW_CTRL: R73.2 U3.23(HW_SW_CTRL)
InternalCLK_N: R53.1 U3.21(OUT1_N)
InternalCLK_P: R43.1 U3.22(OUT1_P)
OE: R72.1 R74.2 U3.11(OE/GPIO4)
REFSEL: R62.2 U3.4(REFSEL)
SCL_I2C: U3.12(SCL/GPIO3) ; port SCL_I2C
SDA_I2C: U3.19(SDA/GPIO2) ; port SDA_I2C
SECREF_N: R63.1 R70.1 U3.2(SECREF_N)
SECREF_P: R60.1 R65.2 R67.2 U3.1(SECREF_P)
SMA_CLK_N: J10.1 R51.1
SMA_CLK_P: J8.1 R45.1
STATUS: R56.1 R58.2 R59.2 U3.20(STATUS/GPIO1)
VDD_REF: C28.1 C29.1 L8.2 U3.3(VDD_REF)
VDD_VCO: C32.1 C33.1 L9.2 U3.24(VDD_VCO)
VDDO_12: C35.1 C36.1 L10.2 U3.15(VDDO_34) U3.16(VDDO_12)
NetC17_1: C17.1 R34.1 R37.2 U1.2(A)
NetC17_2: C17.2 J7.1
NetC21_1: C21.1 C25.1 L7.2 R43.2 R45.2 R47.1 R48.2
NetC23_1: C23.1 J9.1
NetC23_2: C23.2 T5.1
NetC24_2: C24.2 R47.2 R50.1
NetC25_2: C25.2 C26.1 L7.1 R49.2 R50.2 R51.2 R53.2
NetC27_1: C27.1 C31.1 C34.1 L8.1 L9.1 L10.1 R57.2 TP1.1
NetD1_2: D1.2(A) R59.1
NetJ11_1: J11.1 U3.14(OUT3_P)
NetJ12_1: J12.1 U3.10(OUT4_P)
NetR29_1: R29.1 R30.1 Y1.3(OUTPUT) Y2.3(OUT)
NetR31_1: R31.1 R33.2 Y1.1(~{INH})
NetR32_1: R32.1 R35.1 U1.7(Y)
NetR36_1: R36.1 R40.1 U1.6(Z)
NetR38_1: R38.1 R39.2 Y2.1(VC)
NetR42_1: R42.1 R44.2 U1.3(B)
NetR48_1: R48.1 T5.6
NetR49_1: R49.1 T5.4
NetR52_1: R52.1 R55.2 U2.7(SEL)
NetR60_2: R60.2 Y3.1(In/Out)
NetR61_1: R61.1 U3.18(OUT2_P)
NetR63_2: R63.2 Y3.3(Out/In)
NetR64_1: R64.1 U3.17(OUT2_N)
NetR65_1: R65.1 Y4.4(OUT)
NetR66_1: R66.1 R69.2 Y4.1(Control_Volt)
NetR68_1: R68.1 Y4.2(E/D)
NetR71_2: R71.2 U3.8(PDN)

Not connected (* = marked no-connect by the designer): T5 2(NC)*; U1 1(NC)* 4(VBB)*; U2 6(RSVD)*; U3 7(OUT0)* A1(AP)* A2(AP)* A3(AP)* A4(AP)*; Y4 5(NC)*

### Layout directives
differential pair: CLK_N, CLK_P, DCLKIN_CDC_N, DCLKIN_CDC_P, DCLKIN_FPGA_N, DCLKIN_FPGA_P, DCLKIN_N, DCLKIN_P, DCLKIN_SMA_N, DCLKIN_SMA_P, InternalCLK_N, InternalCLK_P, NetR32_1, NetR36_1, SECREF_N, SECREF_P, SMA_CLK_N, SMA_CLK_P

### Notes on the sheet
- (near J9) Shared pads

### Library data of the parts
C17-C20 C22 = CMP-0006607-2: as C53 on sheet DC134_FDA
C21 C23 C26 = CMP-0064970-1: as C1 on sheet DC134_AIN
C24 = CMP-0064970-1: as C37 on sheet DC134_Device
C25 = CMP-0006380-2: CAP, CERM, 39 pF, 25 V, +/- 5%, C0G/NP0, 0402; Manufacturer: MuRata; TaMin_C: -55°C; Polarized: N; SizeAreaWB_mm2: 3; Value1: Unknown; U/M: EA; Value: 39pF; TaMax_C: 125°C; SizeZ_mm: 0.6; SizeX_mm: 1; SizeY_mm: 0.5; AEC Category: Q200
C27 C31 C34 = CMP-0006372-2: CAP, CERM, 1 uF, 6.3 V, +/- 20%, X5R, 0402; Manufacturer: MuRata; TaMin_C: -55°C; Polarized: N; SizeAreaWB_mm2: 3; Value1: Unknown; U/M: EA; Value: 1uF; TaMax_C: 85°C; SizeZ_mm: 0.6; SizeX_mm: 1; SizeY_mm: 0.5; Cap_F: 1µF; AEC Category: Q200
C28 C32 C35 = CMP-0007347-5: CAP, CERM, 4.7 uF, 25 V, +/- 10%, X5R, 0603; Manufacturer: MuRata; TaMin_C: -55°C; Polarized: N; SizeAreaWB_mm2: 4.68; Value1: Unknown; U/M: EA; Value: 4.7uF; TaMax_C: 85°C; SizeZ_mm: 1; SizeX_mm: 1.6; SizeY_mm: 0.8; SizeArea_mm2: 1.28; Cap_F: 4.7µF; AEC Category: Q200
C29 C30 C33 C36 = CMP-0009719-2: CAP, CERM, 0.1 uF, 25 V, +/- 10%, X5R, 0201; Manufacturer: MuRata; TaMin_C: -55°C; Polarized: N; SizeAreaWB_mm2: 2.08; Value1: Unknown; U/M: EA; Value: 0.1uF; TaMax_C: 85°C; SizeZ_mm: 0.33; SizeX_mm: 0.6; SizeY_mm: 0.3; Cap_Case: 0201; SizeArea_mm2: 0.18; Cap_F: 100nF; AEC Category: Q200
D1 = CMP-0002920-2: LED, Green, SMD; Manufacturer: LiteOn; Io_A: 30mA; Vr_V: 5V; Tjmax_C: 85°C; Value1: W; Angle: 130; Type: AlInGaP
J7 J9 J11 J12 = CMP-0055833-1: as J2 on sheet DC134_AIN
J8 J10 = CMP-0055828-1: as J1 on sheet DC134_AIN
L7 = CMP-0080278-3: Inductor, Multilayer, Air Core, 43 nH, 0.19 A, 1.6 ohm, AEC-Q200 Grade 1, SMD; Manufacturer: MuRata; Irms: 0.19A @ 25C rise; SizeAreaWB_mm2: 3.2; DCR_ohm: 1.6; Value1: 1.6 ohm; Value: 43nH; Imax_A: 190mA; SizeZ_mm: 0.6; SizeX_mm: 1; Value2: 0.19A; AEC Qualified: Y; AEC Category: Q200
L8-L10 = CMP-0077879-1: Ferrite Bead, 120 ohm @ 100 MHz, 1.9 A, 0603; Manufacturer: MuRata; ZTyp@100MHz_Ohm: 120; SizeAreaWB_mm2: 4.68; DCR_ohm: 0.04; Value1: 0.04 ohm; Imax_A: 1.9A; SizeZ_mm: 1.0; SizeX_mm: 1.6; SizeY_mm: 0.8; SizeArea_mm2: 1.28
R29 R30 R47 R50 R65 R67 = CMP-0028028-1: RES, 49.9, 1%, 0.05 W, 0201; Manufacturer: Yageo America; Power_W: 50mW; TempCo: 200 ppm/C; Value_Code: 49R9; U/M: EA; Value: 49.9; EIA_Code: E96; SizeX_mm: 0.6; SizeY_mm: 0.3; SizeZ_mm: 0.26; Value2: 0.05W; SizeArea_mm2: 0.18; CompType: Resistor; AEC Qualified: N; VDC_V: 25V; AEC Category: Q200
R31-R33 R35 R36 R40 R41 R43 R45 R51-R55 R60 R61 R63 R64 R68 R70 = CMP-0027008-4: as R1 on sheet DC134_AIN
R34 R42 = CMP-0026453-2: RES, 56.2 k, 1%, 0.063 W, AEC-Q200 Grade 0, 0402; Manufacturer: Vishay-Dale; Power_W: 63mW; TempCo: 100 ppm/C; Value_Code: 56k2; Value: 56.2k; EIA_Code: E96; SizeX_mm: 1; SizeY_mm: 0.5; SizeZ_mm: 0.6; Value2: 0.063W; AEC Qualified: Y; VDC_V: 50V; AEC Category: Q200; AEC Grade: 0
R37 R44 = CMP-0026196-2: RES, 24.9 k, 1%, 0.063 W, AEC-Q200 Grade 0, 0402; Manufacturer: Vishay-Dale; Power_W: 63mW; TempCo: 100 ppm/C; Value_Code: 24k9; Value: 24.9k; EIA_Code: E96; SizeX_mm: 1; SizeY_mm: 0.5; SizeZ_mm: 0.6; Value2: 0.063W; AEC Qualified: Y; VDC_V: 50V; AEC Category: Q200; AEC Grade: 0
R38 R39 R66 R69 = CMP-0027453-1: RES, 1.00 k, 1%, 0.05 W, 0201; Manufacturer: Yageo America; Power_W: 50mW; TempCo: 200 ppm/C; Value_Code: 1k00; U/M: EA; Value: 1.00k; EIA_Code: E96; Res_ohm: 1k; SizeX_mm: 0.6; SizeY_mm: 0.3; SizeZ_mm: 0.26; Value2: 0.05W; SizeArea_mm2: 0.18; AEC Qualified: N; VDC_V: 25V; AEC Category: Q200
R46 = CMP-0028028-1: RES, 49.9, 1%, 0.05 W, 0201; Manufacturer: Yageo America; Power_W: 50mW; TempCo: 200 ppm/C; Value_Code: 49R9; U/M: EA; Value: 49.9; EIA_Code: E96; SizeX_mm: 0.6; SizeY_mm: 0.3; SizeZ_mm: 0.26; Value2: 0.05W; SizeArea_mm2: 0.18; AEC Qualified: N; VDC_V: 25V; AEC Category: Q200
R48 R49 = CMP-0027946-1: RES, 10.0, 1%, 0.05 W, 0201; Manufacturer: Yageo America; Power_W: 50mW; TempCo: 350 ppm/C; Value_Code: 10R0; U/M: EA; Value: 10.0; EIA_Code: E96; Res_ohm: 10; SizeX_mm: 0.6; SizeY_mm: 0.3; SizeZ_mm: 0.26; Value2: 0.05W; SizeArea_mm2: 0.18; CompType: Resistor; AEC Qualified: N; VDC_V: 25V; AEC Category: Q200
R56 R58 R62 R71-R74 = CMP-0028031-1: RES, 4.70 k, 1%, 0.05 W, 0201; Manufacturer: Yageo America; Power_W: 50mW; TempCo: 200 ppm/C; Value_Code: 4k70; U/M: EA; Value: 4.70k; Res_ohm: 4.7k; SizeX_mm: 0.6; SizeY_mm: 0.3; SizeZ_mm: 0.26; Value2: 0.05W; SizeArea_mm2: 0.18; AEC Qualified: N; VDC_V: 25V; AEC Category: Q200
R57 = CMP-0023343-3: RES, 0, 1%, 0.1 W, AEC-Q200 Grade 0, 0603; Manufacturer: Stackpole Electronics Inc; Power_W: 100mW; TempCo: ppm/C; U/M: EA; Value: 0; SizeX_mm: 1.6; SizeY_mm: 0.8; SizeZ_mm: 1; Value2: 0.1W; SizeArea_mm2: 1.28; AEC Qualified: Y; AEC Category: Q200
R59 = CMP-0026725-1: RES, 1.00 k, 1%, 0.0625 W, 0402; Manufacturer: Yageo America; Power_W: 62.5mW; TempCo: 100 ppm/C; Value_Code: 1k00; U/M: EA; Value: 1.00k; EIA_Code: E96; Res_ohm: 1k; SizeX_mm: 1; SizeY_mm: 0.5; SizeZ_mm: 0.6; AEC Qualified: N; VDC_V: 50V; AEC Category: Q200
T5 = CMP-0086669-1: Transformer 50Ω/0.03 to 125 MHz; Manufacturer: Mini-Circuits; Rsec1_ohm: 50; Ns1toNp: 1:1; SizeZ_mm: .206inch; AEC Qualified: No
TP1 = CMP-0055148-1: as TP3 on sheet DC134_Device
U1 = CMP-0076021-1: 2 Gbps LVDS/LVPECL/CML to LVDS Repeater/Translator, DGK0008A (VSSOP-8); Manufacturer: Texas Instruments; SizeAreaWB_mm2: 35.955; SizeArea_mm2: 15.655; SizeZ_mm: 1.1; SizeY_mm: 3.1; U/M: EA; CompType: IC; SizeX_mm: 5.05
U2 = CMP-0074453-1: One Channel Differential 2:1 Mux/Demux, RWA0014A (WQFN-14); Alternate Manufacturer: Texas Instruments; SizeAreaWB_mm2: 20.25; U/M: EA; SizeZ_mm: 0.8; SizeX_mm: 3.5; SizeArea_mm2: 12.25; CompType: IC
U3 = CMP-0750065-2: CDCE6214WRGERQ1, RGE0024P (VQFN-24); Alternate PartNumber: CDCE6214WRGETQ1; Alternate Manufacturer: Texas Instruments; AEC Qualified: Y; SizeArea_mm2: 16; SizeAreaWB_mm2: 25; SizeX_mm: 4; CompType: IC; AEC Category: Q200; SizeZ_mm: 0.9
Y1 = CMP-0006126-3: Clock Oscillator, 19.2 MHz, CMOS, 3.3V, SMD; Manufacturer: Kyocera; TaMin_C: -40°C; Frequency Stability: +/-50ppm; SizeAreaWB_mm2: 14.7; TaMax_C: 85°C; SizeZ_mm: 1; SizeX_mm: 2.5; SizeY_mm: 3.2; SizeArea_mm2: 8
Y2 = CMP-0083654-1: Oscillator, 125 MHz, 15 pF, SMD; Manufacturer: Abracon Corporation; TaMin_C: -40°C; Frequency Stability: 12 ppm; SizeAreaWB_mm2: 174.41; Load Capacitance: 15 pF; Frequency_Fixed: 125MHz; TaMax_C: 85°C; SizeZ_mm: 5.5; SizeX_mm: 8.7; SizeY_mm: 14.3; SizeArea_mm2: 124.41; AEC Qualified: N; AEC Category: Q200
Y3 = CMP-0090315-1: Crystal 10MHz ±25ppm (Tol) ±30ppm (Stability) 12pF FUND 100Ohm 4-Pin Mini-CSMD T/R; Manufacturer: ECS; Esr: 100; AEC Qualified: No; SizeZ_mm: 0.8mm
Y4 = CMP-0088179-1: Ultra-low Phase Noise VCXO with Standby Mode; Manufacturer: Crystek Corporation; Load Capacitance: 15pF; AEC Qualified: No; SizeZ_mm: 5.3mm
